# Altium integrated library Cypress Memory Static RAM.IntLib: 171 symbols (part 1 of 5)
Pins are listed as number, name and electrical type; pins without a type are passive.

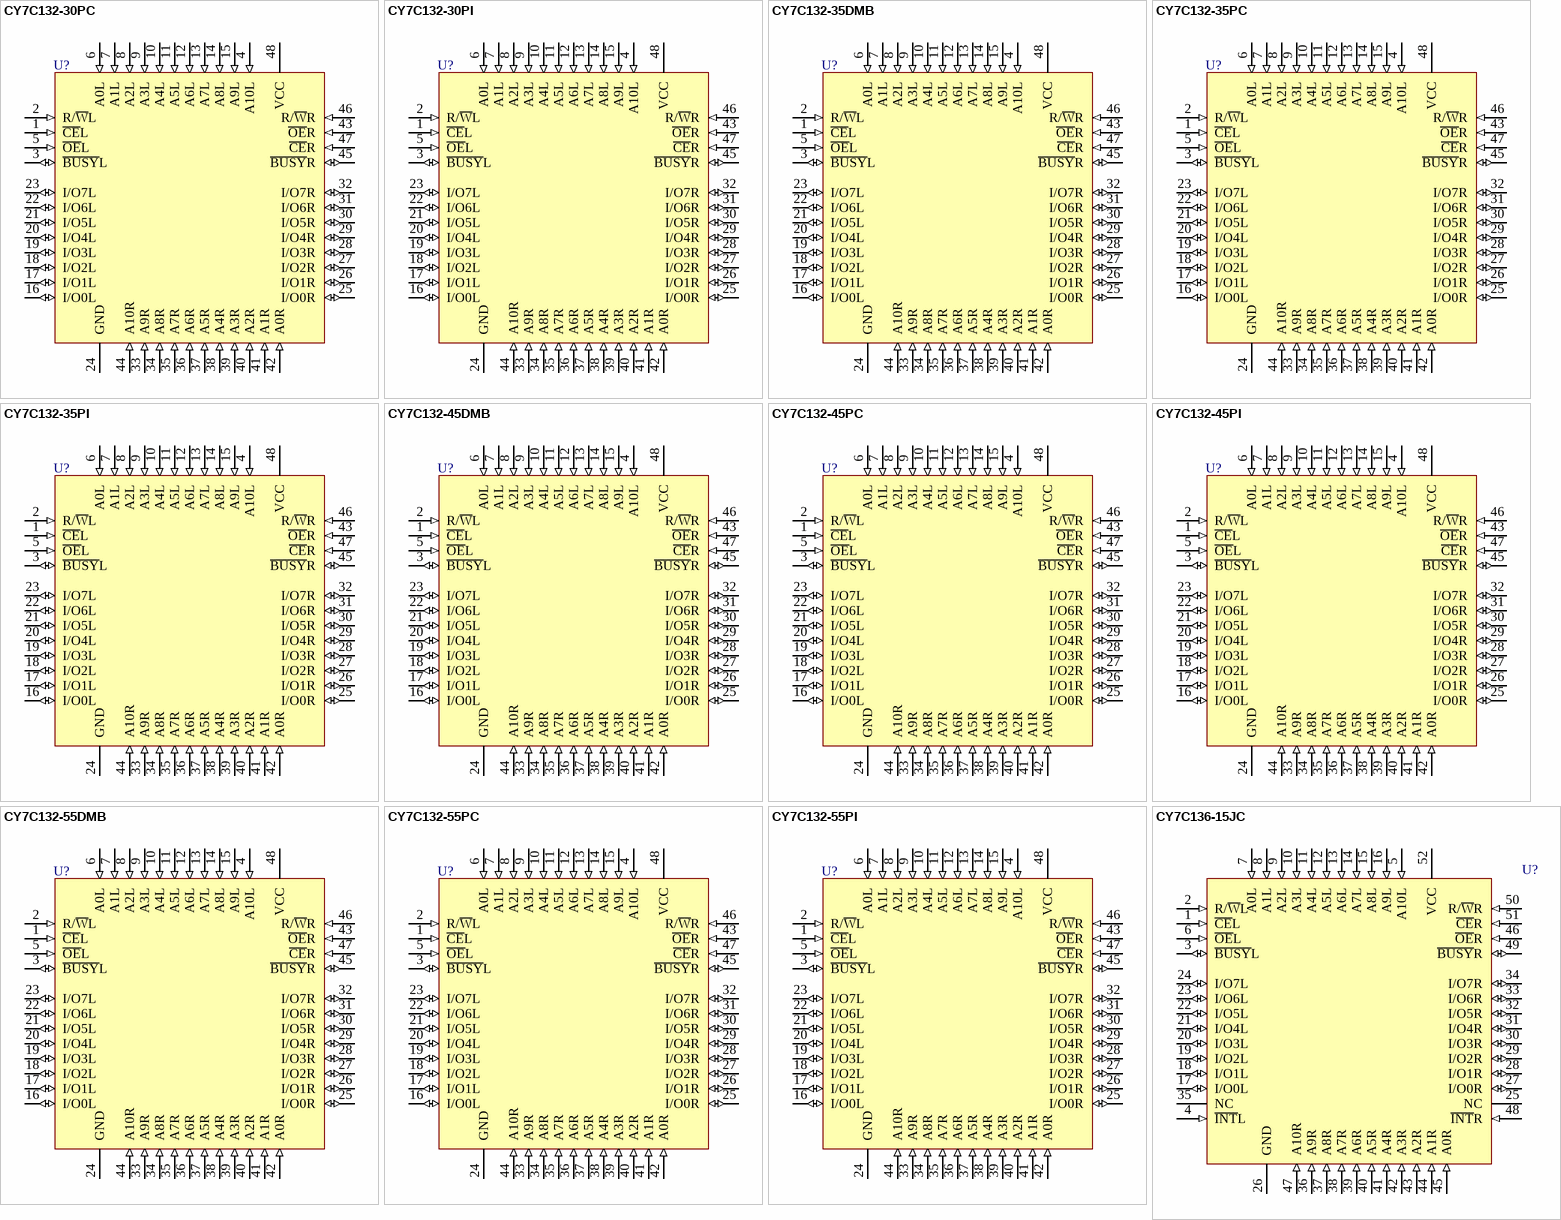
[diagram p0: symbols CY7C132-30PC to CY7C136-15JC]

## CY7C132-30PC
designator U?
2K x 8 Dual-Port Static RAM
footprint P25 (DIP, Molded; 48 Leads; Row Spacing 15.24 mm; Pitch 2.54 mm)
3D model P25 (DIP, Molded; 48 Leads; Row Spacing 15.24 mm; Pitch 2.54 mm)
pins: 1 ~{CE}L (in), 2 R/~{W}L (in), 3 ~{BUSY}L (io), 4 A10L (in), 5 ~{OE}L (in), 6 A0L (in), 7 A1L (in), 8 A2L (in), 9 A3L (in), 10 A4L (in), 11 A5L (in), 12 A6L (in), 13 A7L (in), 14 A8L (in), 15 A9L (in), 16 I/O0L (io), 17 I/O1L (io), 18 I/O2L (io), 19 I/O3L (io), 20 I/O4L (io), 21 I/O5L (io), 22 I/O6L (io), 23 I/O7L (io), 24 GND (power), 25 I/O0R (io), 26 I/O1R (io), 27 I/O2R (io), 28 I/O3R (io), 29 I/O4R (io), 30 I/O5R (io), 31 I/O6R (io), 32 I/O7R (io), 33 A9R (in), 34 A8R (in), 35 A7R (in), 36 A6R (in), 37 A5R (in), 38 A4R (in), 39 A3R (in), 40 A2R (in), 41 A1R (in), 42 A0R (in), 43 ~{OE}R (in), 44 A10R (in), 45 ~{BUSY}R (io), 46 R/~{W}R (in), 47 ~{CE}R (in), 48 VCC (power)

## CY7C132-30PI
designator U?
2K x 8 Dual-Port Static RAM
footprint P25 (DIP, Molded; 48 Leads; Row Spacing 15.24 mm; Pitch 2.54 mm)
3D model P25 (DIP, Molded; 48 Leads; Row Spacing 15.24 mm; Pitch 2.54 mm)
pins: 1 ~{CE}L (in), 2 R/~{W}L (in), 3 ~{BUSY}L (io), 4 A10L (in), 5 ~{OE}L (in), 6 A0L (in), 7 A1L (in), 8 A2L (in), 9 A3L (in), 10 A4L (in), 11 A5L (in), 12 A6L (in), 13 A7L (in), 14 A8L (in), 15 A9L (in), 16 I/O0L (io), 17 I/O1L (io), 18 I/O2L (io), 19 I/O3L (io), 20 I/O4L (io), 21 I/O5L (io), 22 I/O6L (io), 23 I/O7L (io), 24 GND (power), 25 I/O0R (io), 26 I/O1R (io), 27 I/O2R (io), 28 I/O3R (io), 29 I/O4R (io), 30 I/O5R (io), 31 I/O6R (io), 32 I/O7R (io), 33 A9R (in), 34 A8R (in), 35 A7R (in), 36 A6R (in), 37 A5R (in), 38 A4R (in), 39 A3R (in), 40 A2R (in), 41 A1R (in), 42 A0R (in), 43 ~{OE}R (in), 44 A10R (in), 45 ~{BUSY}R (io), 46 R/~{W}R (in), 47 ~{CE}R (in), 48 VCC (power)

## CY7C132-35DMB
designator U?
2K x 8 Dual-Port Static RAM
footprint D26 (DIP, Sidebraze; 48 Leads; Row Spacing 15.24 mm; Pitch 2.54 mm)
3D model P25 (DIP, Sidebraze; 48 Leads; Row Spacing 15.24 mm; Pitch 2.54 mm)
pins: 1 ~{CE}L (in), 2 R/~{W}L (in), 3 ~{BUSY}L (io), 4 A10L (in), 5 ~{OE}L (in), 6 A0L (in), 7 A1L (in), 8 A2L (in), 9 A3L (in), 10 A4L (in), 11 A5L (in), 12 A6L (in), 13 A7L (in), 14 A8L (in), 15 A9L (in), 16 I/O0L (io), 17 I/O1L (io), 18 I/O2L (io), 19 I/O3L (io), 20 I/O4L (io), 21 I/O5L (io), 22 I/O6L (io), 23 I/O7L (io), 24 GND (power), 25 I/O0R (io), 26 I/O1R (io), 27 I/O2R (io), 28 I/O3R (io), 29 I/O4R (io), 30 I/O5R (io), 31 I/O6R (io), 32 I/O7R (io), 33 A9R (in), 34 A8R (in), 35 A7R (in), 36 A6R (in), 37 A5R (in), 38 A4R (in), 39 A3R (in), 40 A2R (in), 41 A1R (in), 42 A0R (in), 43 ~{OE}R (in), 44 A10R (in), 45 ~{BUSY}R (io), 46 R/~{W}R (in), 47 ~{CE}R (in), 48 VCC (power)

## CY7C132-35PC
designator U?
2K x 8 Dual-Port Static RAM
footprint P25 (DIP, Molded; 48 Leads; Row Spacing 15.24 mm; Pitch 2.54 mm)
3D model P25 (DIP, Molded; 48 Leads; Row Spacing 15.24 mm; Pitch 2.54 mm)
pins: 1 ~{CE}L (in), 2 R/~{W}L (in), 3 ~{BUSY}L (io), 4 A10L (in), 5 ~{OE}L (in), 6 A0L (in), 7 A1L (in), 8 A2L (in), 9 A3L (in), 10 A4L (in), 11 A5L (in), 12 A6L (in), 13 A7L (in), 14 A8L (in), 15 A9L (in), 16 I/O0L (io), 17 I/O1L (io), 18 I/O2L (io), 19 I/O3L (io), 20 I/O4L (io), 21 I/O5L (io), 22 I/O6L (io), 23 I/O7L (io), 24 GND (power), 25 I/O0R (io), 26 I/O1R (io), 27 I/O2R (io), 28 I/O3R (io), 29 I/O4R (io), 30 I/O5R (io), 31 I/O6R (io), 32 I/O7R (io), 33 A9R (in), 34 A8R (in), 35 A7R (in), 36 A6R (in), 37 A5R (in), 38 A4R (in), 39 A3R (in), 40 A2R (in), 41 A1R (in), 42 A0R (in), 43 ~{OE}R (in), 44 A10R (in), 45 ~{BUSY}R (io), 46 R/~{W}R (in), 47 ~{CE}R (in), 48 VCC (power)

## CY7C132-35PI
designator U?
2K x 8 Dual-Port Static RAM
footprint P25 (DIP, Molded; 48 Leads; Row Spacing 15.24 mm; Pitch 2.54 mm)
3D model P25 (DIP, Molded; 48 Leads; Row Spacing 15.24 mm; Pitch 2.54 mm)
pins: 1 ~{CE}L (in), 2 R/~{W}L (in), 3 ~{BUSY}L (io), 4 A10L (in), 5 ~{OE}L (in), 6 A0L (in), 7 A1L (in), 8 A2L (in), 9 A3L (in), 10 A4L (in), 11 A5L (in), 12 A6L (in), 13 A7L (in), 14 A8L (in), 15 A9L (in), 16 I/O0L (io), 17 I/O1L (io), 18 I/O2L (io), 19 I/O3L (io), 20 I/O4L (io), 21 I/O5L (io), 22 I/O6L (io), 23 I/O7L (io), 24 GND (power), 25 I/O0R (io), 26 I/O1R (io), 27 I/O2R (io), 28 I/O3R (io), 29 I/O4R (io), 30 I/O5R (io), 31 I/O6R (io), 32 I/O7R (io), 33 A9R (in), 34 A8R (in), 35 A7R (in), 36 A6R (in), 37 A5R (in), 38 A4R (in), 39 A3R (in), 40 A2R (in), 41 A1R (in), 42 A0R (in), 43 ~{OE}R (in), 44 A10R (in), 45 ~{BUSY}R (io), 46 R/~{W}R (in), 47 ~{CE}R (in), 48 VCC (power)

## CY7C132-45DMB
designator U?
2K x 8 Dual-Port Static RAM
footprint D26 (DIP, Sidebraze; 48 Leads; Row Spacing 15.24 mm; Pitch 2.54 mm)
3D model P25 (DIP, Sidebraze; 48 Leads; Row Spacing 15.24 mm; Pitch 2.54 mm)
pins: 1 ~{CE}L (in), 2 R/~{W}L (in), 3 ~{BUSY}L (io), 4 A10L (in), 5 ~{OE}L (in), 6 A0L (in), 7 A1L (in), 8 A2L (in), 9 A3L (in), 10 A4L (in), 11 A5L (in), 12 A6L (in), 13 A7L (in), 14 A8L (in), 15 A9L (in), 16 I/O0L (io), 17 I/O1L (io), 18 I/O2L (io), 19 I/O3L (io), 20 I/O4L (io), 21 I/O5L (io), 22 I/O6L (io), 23 I/O7L (io), 24 GND (power), 25 I/O0R (io), 26 I/O1R (io), 27 I/O2R (io), 28 I/O3R (io), 29 I/O4R (io), 30 I/O5R (io), 31 I/O6R (io), 32 I/O7R (io), 33 A9R (in), 34 A8R (in), 35 A7R (in), 36 A6R (in), 37 A5R (in), 38 A4R (in), 39 A3R (in), 40 A2R (in), 41 A1R (in), 42 A0R (in), 43 ~{OE}R (in), 44 A10R (in), 45 ~{BUSY}R (io), 46 R/~{W}R (in), 47 ~{CE}R (in), 48 VCC (power)

## CY7C132-45PC
designator U?
2K x 8 Dual-Port Static RAM
footprint P25 (DIP, Molded; 48 Leads; Row Spacing 15.24 mm; Pitch 2.54 mm)
3D model P25 (DIP, Molded; 48 Leads; Row Spacing 15.24 mm; Pitch 2.54 mm)
pins: 1 ~{CE}L (in), 2 R/~{W}L (in), 3 ~{BUSY}L (io), 4 A10L (in), 5 ~{OE}L (in), 6 A0L (in), 7 A1L (in), 8 A2L (in), 9 A3L (in), 10 A4L (in), 11 A5L (in), 12 A6L (in), 13 A7L (in), 14 A8L (in), 15 A9L (in), 16 I/O0L (io), 17 I/O1L (io), 18 I/O2L (io), 19 I/O3L (io), 20 I/O4L (io), 21 I/O5L (io), 22 I/O6L (io), 23 I/O7L (io), 24 GND (power), 25 I/O0R (io), 26 I/O1R (io), 27 I/O2R (io), 28 I/O3R (io), 29 I/O4R (io), 30 I/O5R (io), 31 I/O6R (io), 32 I/O7R (io), 33 A9R (in), 34 A8R (in), 35 A7R (in), 36 A6R (in), 37 A5R (in), 38 A4R (in), 39 A3R (in), 40 A2R (in), 41 A1R (in), 42 A0R (in), 43 ~{OE}R (in), 44 A10R (in), 45 ~{BUSY}R (io), 46 R/~{W}R (in), 47 ~{CE}R (in), 48 VCC (power)

## CY7C132-45PI
designator U?
2K x 8 Dual-Port Static RAM
footprint P25 (DIP, Molded; 48 Leads; Row Spacing 15.24 mm; Pitch 2.54 mm)
3D model P25 (DIP, Molded; 48 Leads; Row Spacing 15.24 mm; Pitch 2.54 mm)
pins: 1 ~{CE}L (in), 2 R/~{W}L (in), 3 ~{BUSY}L (io), 4 A10L (in), 5 ~{OE}L (in), 6 A0L (in), 7 A1L (in), 8 A2L (in), 9 A3L (in), 10 A4L (in), 11 A5L (in), 12 A6L (in), 13 A7L (in), 14 A8L (in), 15 A9L (in), 16 I/O0L (io), 17 I/O1L (io), 18 I/O2L (io), 19 I/O3L (io), 20 I/O4L (io), 21 I/O5L (io), 22 I/O6L (io), 23 I/O7L (io), 24 GND (power), 25 I/O0R (io), 26 I/O1R (io), 27 I/O2R (io), 28 I/O3R (io), 29 I/O4R (io), 30 I/O5R (io), 31 I/O6R (io), 32 I/O7R (io), 33 A9R (in), 34 A8R (in), 35 A7R (in), 36 A6R (in), 37 A5R (in), 38 A4R (in), 39 A3R (in), 40 A2R (in), 41 A1R (in), 42 A0R (in), 43 ~{OE}R (in), 44 A10R (in), 45 ~{BUSY}R (io), 46 R/~{W}R (in), 47 ~{CE}R (in), 48 VCC (power)

## CY7C132-55DMB
designator U?
2K x 8 Dual-Port Static RAM
footprint D26 (DIP, Sidebraze; 48 Leads; Row Spacing 15.24 mm; Pitch 2.54 mm)
3D model P25 (DIP, Sidebraze; 48 Leads; Row Spacing 15.24 mm; Pitch 2.54 mm)
pins: 1 ~{CE}L (in), 2 R/~{W}L (in), 3 ~{BUSY}L (io), 4 A10L (in), 5 ~{OE}L (in), 6 A0L (in), 7 A1L (in), 8 A2L (in), 9 A3L (in), 10 A4L (in), 11 A5L (in), 12 A6L (in), 13 A7L (in), 14 A8L (in), 15 A9L (in), 16 I/O0L (io), 17 I/O1L (io), 18 I/O2L (io), 19 I/O3L (io), 20 I/O4L (io), 21 I/O5L (io), 22 I/O6L (io), 23 I/O7L (io), 24 GND (power), 25 I/O0R (io), 26 I/O1R (io), 27 I/O2R (io), 28 I/O3R (io), 29 I/O4R (io), 30 I/O5R (io), 31 I/O6R (io), 32 I/O7R (io), 33 A9R (in), 34 A8R (in), 35 A7R (in), 36 A6R (in), 37 A5R (in), 38 A4R (in), 39 A3R (in), 40 A2R (in), 41 A1R (in), 42 A0R (in), 43 ~{OE}R (in), 44 A10R (in), 45 ~{BUSY}R (io), 46 R/~{W}R (in), 47 ~{CE}R (in), 48 VCC (power)

## CY7C132-55PC
designator U?
2K x 8 Dual-Port Static RAM
footprint P25 (DIP, Molded; 48 Leads; Row Spacing 15.24 mm; Pitch 2.54 mm)
3D model P25 (DIP, Molded; 48 Leads; Row Spacing 15.24 mm; Pitch 2.54 mm)
pins: 1 ~{CE}L (in), 2 R/~{W}L (in), 3 ~{BUSY}L (io), 4 A10L (in), 5 ~{OE}L (in), 6 A0L (in), 7 A1L (in), 8 A2L (in), 9 A3L (in), 10 A4L (in), 11 A5L (in), 12 A6L (in), 13 A7L (in), 14 A8L (in), 15 A9L (in), 16 I/O0L (io), 17 I/O1L (io), 18 I/O2L (io), 19 I/O3L (io), 20 I/O4L (io), 21 I/O5L (io), 22 I/O6L (io), 23 I/O7L (io), 24 GND (power), 25 I/O0R (io), 26 I/O1R (io), 27 I/O2R (io), 28 I/O3R (io), 29 I/O4R (io), 30 I/O5R (io), 31 I/O6R (io), 32 I/O7R (io), 33 A9R (in), 34 A8R (in), 35 A7R (in), 36 A6R (in), 37 A5R (in), 38 A4R (in), 39 A3R (in), 40 A2R (in), 41 A1R (in), 42 A0R (in), 43 ~{OE}R (in), 44 A10R (in), 45 ~{BUSY}R (io), 46 R/~{W}R (in), 47 ~{CE}R (in), 48 VCC (power)

## CY7C132-55PI
designator U?
2K x 8 Dual-Port Static RAM
footprint P25 (DIP, Molded; 48 Leads; Row Spacing 15.24 mm; Pitch 2.54 mm)
3D model P25 (DIP, Molded; 48 Leads; Row Spacing 15.24 mm; Pitch 2.54 mm)
pins: 1 ~{CE}L (in), 2 R/~{W}L (in), 3 ~{BUSY}L (io), 4 A10L (in), 5 ~{OE}L (in), 6 A0L (in), 7 A1L (in), 8 A2L (in), 9 A3L (in), 10 A4L (in), 11 A5L (in), 12 A6L (in), 13 A7L (in), 14 A8L (in), 15 A9L (in), 16 I/O0L (io), 17 I/O1L (io), 18 I/O2L (io), 19 I/O3L (io), 20 I/O4L (io), 21 I/O5L (io), 22 I/O6L (io), 23 I/O7L (io), 24 GND (power), 25 I/O0R (io), 26 I/O1R (io), 27 I/O2R (io), 28 I/O3R (io), 29 I/O4R (io), 30 I/O5R (io), 31 I/O6R (io), 32 I/O7R (io), 33 A9R (in), 34 A8R (in), 35 A7R (in), 36 A6R (in), 37 A5R (in), 38 A4R (in), 39 A3R (in), 40 A2R (in), 41 A1R (in), 42 A0R (in), 43 ~{OE}R (in), 44 A10R (in), 45 ~{BUSY}R (io), 46 R/~{W}R (in), 47 ~{CE}R (in), 48 VCC (power)

## CY7C136-15JC
designator U?
2K x 8 Dual-Port Static RAM
footprint J69_N (Leaded Chip Carrier, 52-Leads, Body 19x19mm, Pitch 1.27mm, IPC Medium Density)
footprint J69_L (Leaded Chip Carrier, 52-Leads, Body 19x19mm, Pitch 1.27mm, IPC High Density)
footprint J69_M (Leaded Chip Carrier, 52-Leads, Body 19x19mm, Pitch 1.27mm, IPC Low Density)
3D model CY7C136-J69 (52-Pin Plastic Leaded Chip Carrier 1.27 mm Pitch)
pins: 1 ~{CE}L (in), 2 R/~{W}L (in), 3 ~{BUSY}L (io), 4 ~{INT}L (in), 5 A10L (in), 6 ~{OE}L (in), 7 A0L (in), 8 A1L (in), 9 A2L (in), 10 A3L (in), 11 A4L (in), 12 A5L (in), 13 A6L (in), 14 A7L (in), 15 A8L (in), 16 A9L (in), 17 I/O0L (io), 18 I/O1L (io), 19 I/O2L (io), 20 I/O3L (io), 21 I/O4L (io), 22 I/O5L (io), 23 I/O6L (io), 24 I/O7L (io), 25 NC, 26 GND (power), 27 I/O0R (io), 28 I/O1R (io), 29 I/O2R (io), 30 I/O3R (io), 31 I/O4R (io), 32 I/O5R (io), 33 I/O6R (io), 34 I/O7R (io), 35 NC, 36 A9R (in), 37 A8R (in), 38 A7R (in), 39 A6R (in), 40 A5R (in), 41 A4R (in), 42 A3R (in), 43 A2R (in), 44 A1R (in), 45 A0R (in), 46 ~{OE}R (in), 47 A10R (in), 48 ~{INT}R (in), 49 ~{BUSY}R (io), 50 R/~{W}R (in), 51 ~{CE}R (in), 52 VCC (power)

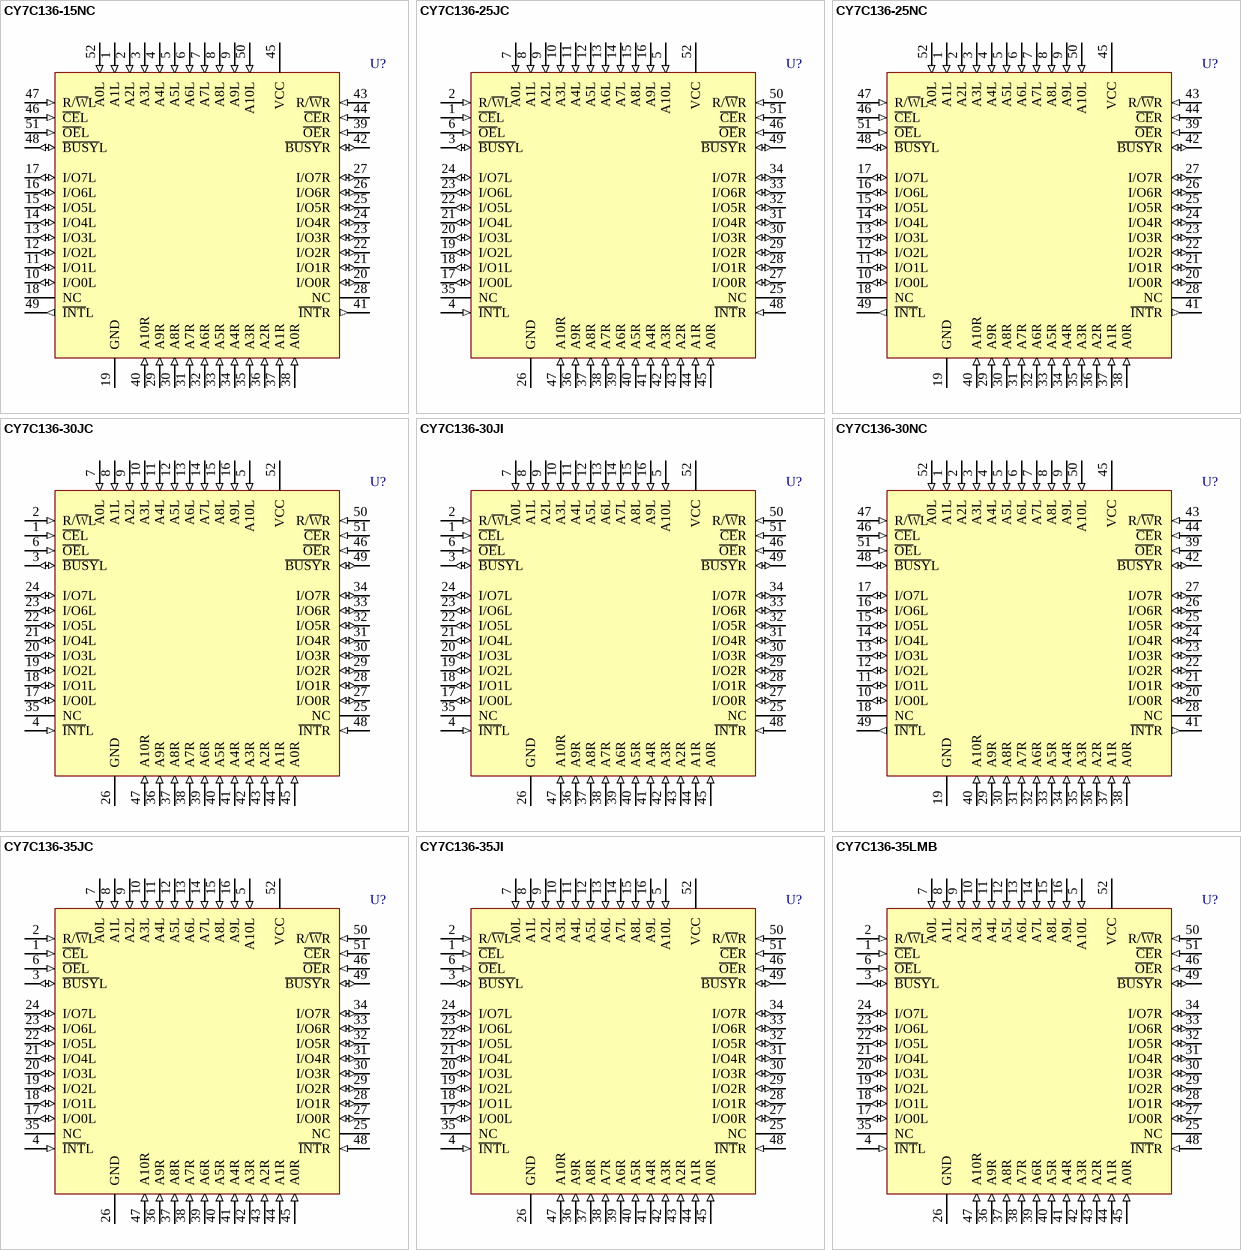
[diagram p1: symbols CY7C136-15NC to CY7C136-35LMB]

## CY7C136-15NC
designator U?
2K x 8 Dual-Port Static RAM
footprint N52_N (QFP, 52-Leads, Body 10 x 10mm, Pitch 0.65mm, IPC Medium Density)
footprint N52_L (QFP, 52-Leads, Body 10 x 10mm, Pitch 0.65mm, IPC High Density)
footprint N52_M (QFP, 52-Leads, Body 10 x 10mm, Pitch 0.65mm, IPC Low Density)
3D model CY7C136-N52 (52-Pin Plastic Quad Flat Pack 0.65 mm Pitch)
pins: 1 A1L (in), 2 A2L (in), 3 A3L (in), 4 A4L (in), 5 A5L (in), 6 A6L (in), 7 A7L (in), 8 A8L (in), 9 A9L (in), 10 I/O0L (io), 11 I/O1L (io), 12 I/O2L (io), 13 I/O3L (io), 14 I/O4L (io), 15 I/O5L (io), 16 I/O6L (io), 17 I/O7L (io), 18 NC, 19 GND (power), 20 I/O0R (io), 21 I/O1R (io), 22 I/O2R (io), 23 I/O3R (io), 24 I/O4R (io), 25 I/O5R (io), 26 I/O6R (io), 27 I/O7R (io), 28 NC, 29 A9R (in), 30 A8R (in), 31 A7R (in), 32 A6R (in), 33 A5R (in), 34 A4R (in), 35 A3R (in), 36 A2R (in), 37 A1R (in), 38 A0R (in), 39 ~{OE}R (in), 40 A10R (in), 41 ~{INT}R (out), 42 ~{BUSY}R (io), 43 R/~{W}R (in), 44 ~{CE}R (in), 45 VCC (power), 46 ~{CE}L (in), 47 R/~{W}L (in), 48 ~{BUSY}L (io), 49 ~{INT}L (out), 50 A10L (in), 51 ~{OE}L (in), 52 A0L (in)

## CY7C136-25JC
designator U?
2K x 8 Dual-Port Static RAM
footprint J69_N (Leaded Chip Carrier, 52-Leads, Body 19x19mm, Pitch 1.27mm, IPC Medium Density)
footprint J69_L (Leaded Chip Carrier, 52-Leads, Body 19x19mm, Pitch 1.27mm, IPC High Density)
footprint J69_M (Leaded Chip Carrier, 52-Leads, Body 19x19mm, Pitch 1.27mm, IPC Low Density)
3D model CY7C136-J69 (52-Pin Plastic Leaded Chip Carrier 1.27 mm Pitch)
pins: 1 ~{CE}L (in), 2 R/~{W}L (in), 3 ~{BUSY}L (io), 4 ~{INT}L (in), 5 A10L (in), 6 ~{OE}L (in), 7 A0L (in), 8 A1L (in), 9 A2L (in), 10 A3L (in), 11 A4L (in), 12 A5L (in), 13 A6L (in), 14 A7L (in), 15 A8L (in), 16 A9L (in), 17 I/O0L (io), 18 I/O1L (io), 19 I/O2L (io), 20 I/O3L (io), 21 I/O4L (io), 22 I/O5L (io), 23 I/O6L (io), 24 I/O7L (io), 25 NC, 26 GND (power), 27 I/O0R (io), 28 I/O1R (io), 29 I/O2R (io), 30 I/O3R (io), 31 I/O4R (io), 32 I/O5R (io), 33 I/O6R (io), 34 I/O7R (io), 35 NC, 36 A9R (in), 37 A8R (in), 38 A7R (in), 39 A6R (in), 40 A5R (in), 41 A4R (in), 42 A3R (in), 43 A2R (in), 44 A1R (in), 45 A0R (in), 46 ~{OE}R (in), 47 A10R (in), 48 ~{INT}R (in), 49 ~{BUSY}R (io), 50 R/~{W}R (in), 51 ~{CE}R (in), 52 VCC (power)

## CY7C136-25NC
designator U?
2K x 8 Dual-Port Static RAM
footprint N52_N (QFP, 52-Leads, Body 10 x 10mm, Pitch 0.65mm, IPC Medium Density)
footprint N52_L (QFP, 52-Leads, Body 10 x 10mm, Pitch 0.65mm, IPC High Density)
footprint N52_M (QFP, 52-Leads, Body 10 x 10mm, Pitch 0.65mm, IPC Low Density)
3D model CY7C136-N52 (52-Pin Plastic Quad Flat Pack 0.65 mm Pitch)
pins: 1 A1L (in), 2 A2L (in), 3 A3L (in), 4 A4L (in), 5 A5L (in), 6 A6L (in), 7 A7L (in), 8 A8L (in), 9 A9L (in), 10 I/O0L (io), 11 I/O1L (io), 12 I/O2L (io), 13 I/O3L (io), 14 I/O4L (io), 15 I/O5L (io), 16 I/O6L (io), 17 I/O7L (io), 18 NC, 19 GND (power), 20 I/O0R (io), 21 I/O1R (io), 22 I/O2R (io), 23 I/O3R (io), 24 I/O4R (io), 25 I/O5R (io), 26 I/O6R (io), 27 I/O7R (io), 28 NC, 29 A9R (in), 30 A8R (in), 31 A7R (in), 32 A6R (in), 33 A5R (in), 34 A4R (in), 35 A3R (in), 36 A2R (in), 37 A1R (in), 38 A0R (in), 39 ~{OE}R (in), 40 A10R (in), 41 ~{INT}R (out), 42 ~{BUSY}R (io), 43 R/~{W}R (in), 44 ~{CE}R (in), 45 VCC (power), 46 ~{CE}L (in), 47 R/~{W}L (in), 48 ~{BUSY}L (io), 49 ~{INT}L (out), 50 A10L (in), 51 ~{OE}L (in), 52 A0L (in)

## CY7C136-30JC
designator U?
2K x 8 Dual-Port Static RAM
footprint J69_N (Leaded Chip Carrier, 52-Leads, Body 19x19mm, Pitch 1.27mm, IPC Medium Density)
footprint J69_L (Leaded Chip Carrier, 52-Leads, Body 19x19mm, Pitch 1.27mm, IPC High Density)
footprint J69_M (Leaded Chip Carrier, 52-Leads, Body 19x19mm, Pitch 1.27mm, IPC Low Density)
3D model CY7C136-J69 (52-Pin Plastic Leaded Chip Carrier 1.27 mm Pitch)
pins: 1 ~{CE}L (in), 2 R/~{W}L (in), 3 ~{BUSY}L (io), 4 ~{INT}L (in), 5 A10L (in), 6 ~{OE}L (in), 7 A0L (in), 8 A1L (in), 9 A2L (in), 10 A3L (in), 11 A4L (in), 12 A5L (in), 13 A6L (in), 14 A7L (in), 15 A8L (in), 16 A9L (in), 17 I/O0L (io), 18 I/O1L (io), 19 I/O2L (io), 20 I/O3L (io), 21 I/O4L (io), 22 I/O5L (io), 23 I/O6L (io), 24 I/O7L (io), 25 NC, 26 GND (power), 27 I/O0R (io), 28 I/O1R (io), 29 I/O2R (io), 30 I/O3R (io), 31 I/O4R (io), 32 I/O5R (io), 33 I/O6R (io), 34 I/O7R (io), 35 NC, 36 A9R (in), 37 A8R (in), 38 A7R (in), 39 A6R (in), 40 A5R (in), 41 A4R (in), 42 A3R (in), 43 A2R (in), 44 A1R (in), 45 A0R (in), 46 ~{OE}R (in), 47 A10R (in), 48 ~{INT}R (in), 49 ~{BUSY}R (io), 50 R/~{W}R (in), 51 ~{CE}R (in), 52 VCC (power)

## CY7C136-30JI
designator U?
2K x 8 Dual-Port Static RAM
footprint J69_N (Leaded Chip Carrier, 52-Leads, Body 19x19mm, Pitch 1.27mm, IPC Medium Density)
footprint J69_L (Leaded Chip Carrier, 52-Leads, Body 19x19mm, Pitch 1.27mm, IPC High Density)
footprint J69_M (Leaded Chip Carrier, 52-Leads, Body 19x19mm, Pitch 1.27mm, IPC Low Density)
3D model CY7C136-J69 (52-Pin Plastic Leaded Chip Carrier 1.27 mm Pitch)
pins: 1 ~{CE}L (in), 2 R/~{W}L (in), 3 ~{BUSY}L (io), 4 ~{INT}L (in), 5 A10L (in), 6 ~{OE}L (in), 7 A0L (in), 8 A1L (in), 9 A2L (in), 10 A3L (in), 11 A4L (in), 12 A5L (in), 13 A6L (in), 14 A7L (in), 15 A8L (in), 16 A9L (in), 17 I/O0L (io), 18 I/O1L (io), 19 I/O2L (io), 20 I/O3L (io), 21 I/O4L (io), 22 I/O5L (io), 23 I/O6L (io), 24 I/O7L (io), 25 NC, 26 GND (power), 27 I/O0R (io), 28 I/O1R (io), 29 I/O2R (io), 30 I/O3R (io), 31 I/O4R (io), 32 I/O5R (io), 33 I/O6R (io), 34 I/O7R (io), 35 NC, 36 A9R (in), 37 A8R (in), 38 A7R (in), 39 A6R (in), 40 A5R (in), 41 A4R (in), 42 A3R (in), 43 A2R (in), 44 A1R (in), 45 A0R (in), 46 ~{OE}R (in), 47 A10R (in), 48 ~{INT}R (in), 49 ~{BUSY}R (io), 50 R/~{W}R (in), 51 ~{CE}R (in), 52 VCC (power)

## CY7C136-30NC
designator U?
2K x 8 Dual-Port Static RAM
footprint N52_N (QFP, 52-Leads, Body 10 x 10mm, Pitch 0.65mm, IPC Medium Density)
footprint N52_L (QFP, 52-Leads, Body 10 x 10mm, Pitch 0.65mm, IPC High Density)
footprint N52_M (QFP, 52-Leads, Body 10 x 10mm, Pitch 0.65mm, IPC Low Density)
3D model CY7C136-N52 (52-Pin Plastic Quad Flat Pack 0.65 mm Pitch)
pins: 1 A1L (in), 2 A2L (in), 3 A3L (in), 4 A4L (in), 5 A5L (in), 6 A6L (in), 7 A7L (in), 8 A8L (in), 9 A9L (in), 10 I/O0L (io), 11 I/O1L (io), 12 I/O2L (io), 13 I/O3L (io), 14 I/O4L (io), 15 I/O5L (io), 16 I/O6L (io), 17 I/O7L (io), 18 NC, 19 GND (power), 20 I/O0R (io), 21 I/O1R (io), 22 I/O2R (io), 23 I/O3R (io), 24 I/O4R (io), 25 I/O5R (io), 26 I/O6R (io), 27 I/O7R (io), 28 NC, 29 A9R (in), 30 A8R (in), 31 A7R (in), 32 A6R (in), 33 A5R (in), 34 A4R (in), 35 A3R (in), 36 A2R (in), 37 A1R (in), 38 A0R (in), 39 ~{OE}R (in), 40 A10R (in), 41 ~{INT}R (out), 42 ~{BUSY}R (io), 43 R/~{W}R (in), 44 ~{CE}R (in), 45 VCC (power), 46 ~{CE}L (in), 47 R/~{W}L (in), 48 ~{BUSY}L (io), 49 ~{INT}L (out), 50 A10L (in), 51 ~{OE}L (in), 52 A0L (in)

## CY7C136-35JC
designator U?
2K x 8 Dual-Port Static RAM
footprint J69_N (Leaded Chip Carrier, 52-Leads, Body 19x19mm, Pitch 1.27mm, IPC Medium Density)
footprint J69_L (Leaded Chip Carrier, 52-Leads, Body 19x19mm, Pitch 1.27mm, IPC High Density)
footprint J69_M (Leaded Chip Carrier, 52-Leads, Body 19x19mm, Pitch 1.27mm, IPC Low Density)
3D model CY7C136-J69 (52-Pin Plastic Leaded Chip Carrier 1.27 mm Pitch)
pins: 1 ~{CE}L (in), 2 R/~{W}L (in), 3 ~{BUSY}L (io), 4 ~{INT}L (in), 5 A10L (in), 6 ~{OE}L (in), 7 A0L (in), 8 A1L (in), 9 A2L (in), 10 A3L (in), 11 A4L (in), 12 A5L (in), 13 A6L (in), 14 A7L (in), 15 A8L (in), 16 A9L (in), 17 I/O0L (io), 18 I/O1L (io), 19 I/O2L (io), 20 I/O3L (io), 21 I/O4L (io), 22 I/O5L (io), 23 I/O6L (io), 24 I/O7L (io), 25 NC, 26 GND (power), 27 I/O0R (io), 28 I/O1R (io), 29 I/O2R (io), 30 I/O3R (io), 31 I/O4R (io), 32 I/O5R (io), 33 I/O6R (io), 34 I/O7R (io), 35 NC, 36 A9R (in), 37 A8R (in), 38 A7R (in), 39 A6R (in), 40 A5R (in), 41 A4R (in), 42 A3R (in), 43 A2R (in), 44 A1R (in), 45 A0R (in), 46 ~{OE}R (in), 47 A10R (in), 48 ~{INT}R (in), 49 ~{BUSY}R (io), 50 R/~{W}R (in), 51 ~{CE}R (in), 52 VCC (power)

## CY7C136-35JI
designator U?
2K x 8 Dual-Port Static RAM
footprint J69_N (Leaded Chip Carrier, 52-Leads, Body 19x19mm, Pitch 1.27mm, IPC Medium Density)
footprint J69_L (Leaded Chip Carrier, 52-Leads, Body 19x19mm, Pitch 1.27mm, IPC High Density)
footprint J69_M (Leaded Chip Carrier, 52-Leads, Body 19x19mm, Pitch 1.27mm, IPC Low Density)
3D model CY7C136-J69 (52-Pin Plastic Leaded Chip Carrier 1.27 mm Pitch)
pins: 1 ~{CE}L (in), 2 R/~{W}L (in), 3 ~{BUSY}L (io), 4 ~{INT}L (in), 5 A10L (in), 6 ~{OE}L (in), 7 A0L (in), 8 A1L (in), 9 A2L (in), 10 A3L (in), 11 A4L (in), 12 A5L (in), 13 A6L (in), 14 A7L (in), 15 A8L (in), 16 A9L (in), 17 I/O0L (io), 18 I/O1L (io), 19 I/O2L (io), 20 I/O3L (io), 21 I/O4L (io), 22 I/O5L (io), 23 I/O6L (io), 24 I/O7L (io), 25 NC, 26 GND (power), 27 I/O0R (io), 28 I/O1R (io), 29 I/O2R (io), 30 I/O3R (io), 31 I/O4R (io), 32 I/O5R (io), 33 I/O6R (io), 34 I/O7R (io), 35 NC, 36 A9R (in), 37 A8R (in), 38 A7R (in), 39 A6R (in), 40 A5R (in), 41 A4R (in), 42 A3R (in), 43 A2R (in), 44 A1R (in), 45 A0R (in), 46 ~{OE}R (in), 47 A10R (in), 48 ~{INT}R (in), 49 ~{BUSY}R (io), 50 R/~{W}R (in), 51 ~{CE}R (in), 52 VCC (power)

## CY7C136-35LMB
designator U?
2K x 8 Dual-Port Static RAM
footprint L69 (Leadless Chip Carrier; 52 Terminals; Body 19.1 x 19.1 mm)
pins: 1 ~{CE}L (in), 2 R/~{W}L (in), 3 ~{BUSY}L (io), 4 ~{INT}L (in), 5 A10L (in), 6 ~{OE}L (in), 7 A0L (in), 8 A1L (in), 9 A2L (in), 10 A3L (in), 11 A4L (in), 12 A5L (in), 13 A6L (in), 14 A7L (in), 15 A8L (in), 16 A9L (in), 17 I/O0L (io), 18 I/O1L (io), 19 I/O2L (io), 20 I/O3L (io), 21 I/O4L (io), 22 I/O5L (io), 23 I/O6L (io), 24 I/O7L (io), 25 NC, 26 GND (power), 27 I/O0R (io), 28 I/O1R (io), 29 I/O2R (io), 30 I/O3R (io), 31 I/O4R (io), 32 I/O5R (io), 33 I/O6R (io), 34 I/O7R (io), 35 NC, 36 A9R (in), 37 A8R (in), 38 A7R (in), 39 A6R (in), 40 A5R (in), 41 A4R (in), 42 A3R (in), 43 A2R (in), 44 A1R (in), 45 A0R (in), 46 ~{OE}R (in), 47 A10R (in), 48 ~{INT}R (in), 49 ~{BUSY}R (io), 50 R/~{W}R (in), 51 ~{CE}R (in), 52 VCC (power)

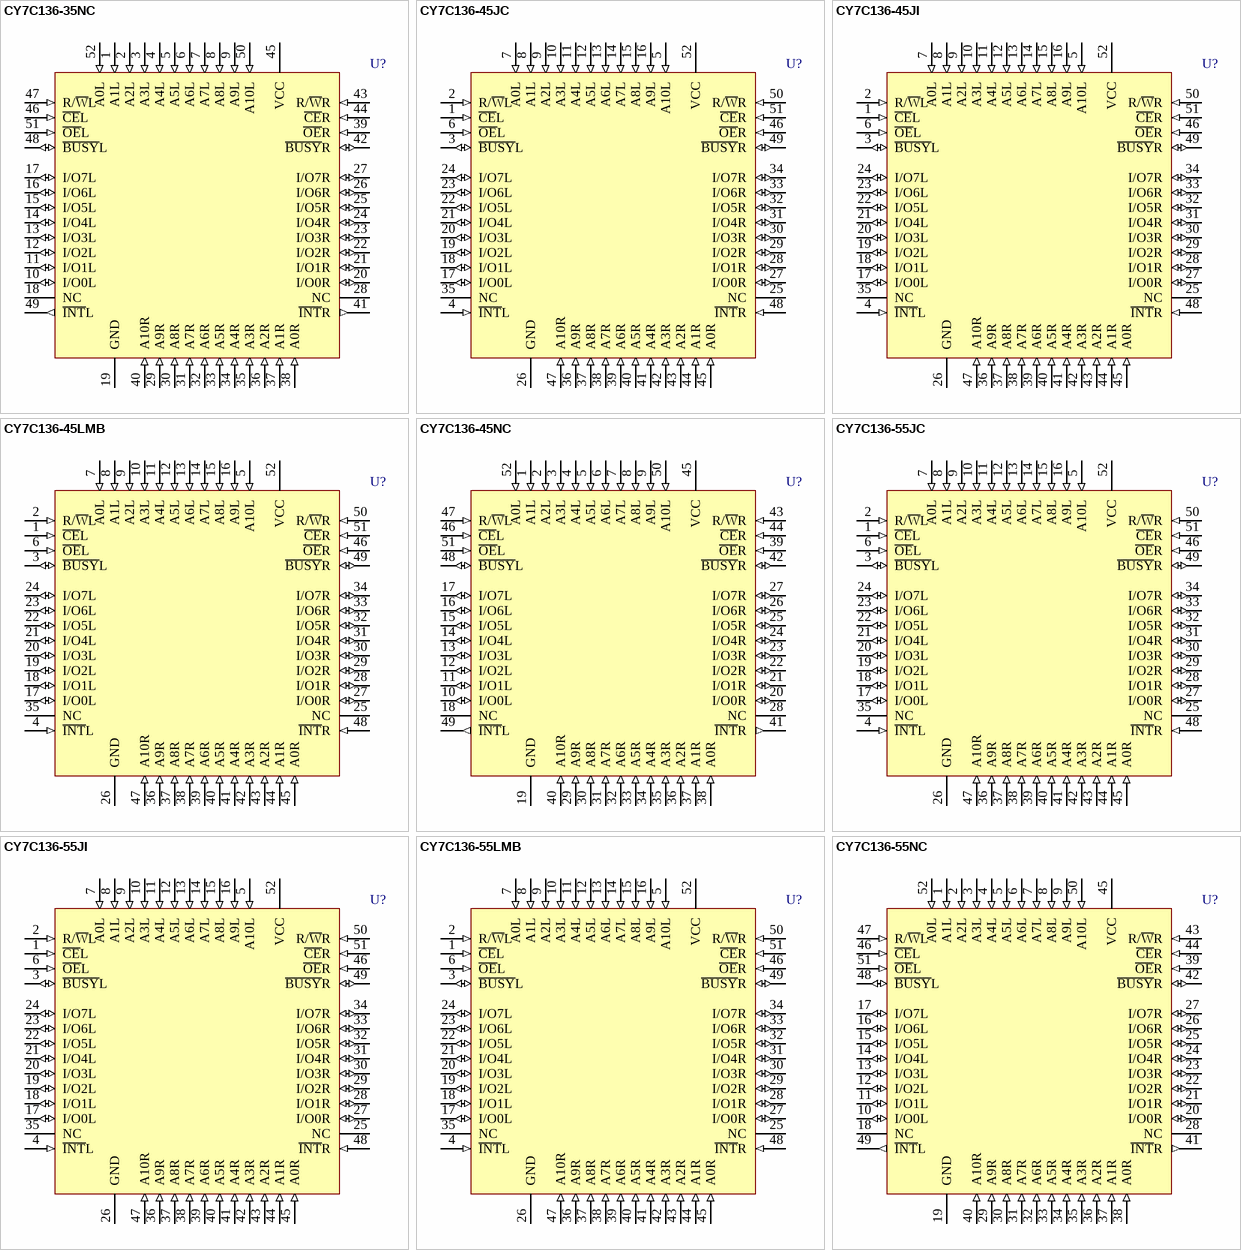
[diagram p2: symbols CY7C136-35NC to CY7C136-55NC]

## CY7C136-35NC
designator U?
2K x 8 Dual-Port Static RAM
footprint N52_N (QFP, 52-Leads, Body 10 x 10mm, Pitch 0.65mm, IPC Medium Density)
footprint N52_L (QFP, 52-Leads, Body 10 x 10mm, Pitch 0.65mm, IPC High Density)
footprint N52_M (QFP, 52-Leads, Body 10 x 10mm, Pitch 0.65mm, IPC Low Density)
3D model CY7C136-N52 (52-Pin Plastic Quad Flat Pack 0.65 mm Pitch)
pins: 1 A1L (in), 2 A2L (in), 3 A3L (in), 4 A4L (in), 5 A5L (in), 6 A6L (in), 7 A7L (in), 8 A8L (in), 9 A9L (in), 10 I/O0L (io), 11 I/O1L (io), 12 I/O2L (io), 13 I/O3L (io), 14 I/O4L (io), 15 I/O5L (io), 16 I/O6L (io), 17 I/O7L (io), 18 NC, 19 GND (power), 20 I/O0R (io), 21 I/O1R (io), 22 I/O2R (io), 23 I/O3R (io), 24 I/O4R (io), 25 I/O5R (io), 26 I/O6R (io), 27 I/O7R (io), 28 NC, 29 A9R (in), 30 A8R (in), 31 A7R (in), 32 A6R (in), 33 A5R (in), 34 A4R (in), 35 A3R (in), 36 A2R (in), 37 A1R (in), 38 A0R (in), 39 ~{OE}R (in), 40 A10R (in), 41 ~{INT}R (out), 42 ~{BUSY}R (io), 43 R/~{W}R (in), 44 ~{CE}R (in), 45 VCC (power), 46 ~{CE}L (in), 47 R/~{W}L (in), 48 ~{BUSY}L (io), 49 ~{INT}L (out), 50 A10L (in), 51 ~{OE}L (in), 52 A0L (in)

## CY7C136-45JC
designator U?
2K x 8 Dual-Port Static RAM
footprint J69_N (Leaded Chip Carrier, 52-Leads, Body 19x19mm, Pitch 1.27mm, IPC Medium Density)
footprint J69_L (Leaded Chip Carrier, 52-Leads, Body 19x19mm, Pitch 1.27mm, IPC High Density)
footprint J69_M (Leaded Chip Carrier, 52-Leads, Body 19x19mm, Pitch 1.27mm, IPC Low Density)
3D model CY7C136-J69 (52-Pin Plastic Leaded Chip Carrier 1.27 mm Pitch)
pins: 1 ~{CE}L (in), 2 R/~{W}L (in), 3 ~{BUSY}L (io), 4 ~{INT}L (in), 5 A10L (in), 6 ~{OE}L (in), 7 A0L (in), 8 A1L (in), 9 A2L (in), 10 A3L (in), 11 A4L (in), 12 A5L (in), 13 A6L (in), 14 A7L (in), 15 A8L (in), 16 A9L (in), 17 I/O0L (io), 18 I/O1L (io), 19 I/O2L (io), 20 I/O3L (io), 21 I/O4L (io), 22 I/O5L (io), 23 I/O6L (io), 24 I/O7L (io), 25 NC, 26 GND (power), 27 I/O0R (io), 28 I/O1R (io), 29 I/O2R (io), 30 I/O3R (io), 31 I/O4R (io), 32 I/O5R (io), 33 I/O6R (io), 34 I/O7R (io), 35 NC, 36 A9R (in), 37 A8R (in), 38 A7R (in), 39 A6R (in), 40 A5R (in), 41 A4R (in), 42 A3R (in), 43 A2R (in), 44 A1R (in), 45 A0R (in), 46 ~{OE}R (in), 47 A10R (in), 48 ~{INT}R (in), 49 ~{BUSY}R (io), 50 R/~{W}R (in), 51 ~{CE}R (in), 52 VCC (power)

## CY7C136-45JI
designator U?
2K x 8 Dual-Port Static RAM
footprint J69_N (Leaded Chip Carrier, 52-Leads, Body 19x19mm, Pitch 1.27mm, IPC Medium Density)
footprint J69_L (Leaded Chip Carrier, 52-Leads, Body 19x19mm, Pitch 1.27mm, IPC High Density)
footprint J69_M (Leaded Chip Carrier, 52-Leads, Body 19x19mm, Pitch 1.27mm, IPC Low Density)
3D model CY7C136-J69 (52-Pin Plastic Leaded Chip Carrier 1.27 mm Pitch)
pins: 1 ~{CE}L (in), 2 R/~{W}L (in), 3 ~{BUSY}L (io), 4 ~{INT}L (in), 5 A10L (in), 6 ~{OE}L (in), 7 A0L (in), 8 A1L (in), 9 A2L (in), 10 A3L (in), 11 A4L (in), 12 A5L (in), 13 A6L (in), 14 A7L (in), 15 A8L (in), 16 A9L (in), 17 I/O0L (io), 18 I/O1L (io), 19 I/O2L (io), 20 I/O3L (io), 21 I/O4L (io), 22 I/O5L (io), 23 I/O6L (io), 24 I/O7L (io), 25 NC, 26 GND (power), 27 I/O0R (io), 28 I/O1R (io), 29 I/O2R (io), 30 I/O3R (io), 31 I/O4R (io), 32 I/O5R (io), 33 I/O6R (io), 34 I/O7R (io), 35 NC, 36 A9R (in), 37 A8R (in), 38 A7R (in), 39 A6R (in), 40 A5R (in), 41 A4R (in), 42 A3R (in), 43 A2R (in), 44 A1R (in), 45 A0R (in), 46 ~{OE}R (in), 47 A10R (in), 48 ~{INT}R (in), 49 ~{BUSY}R (io), 50 R/~{W}R (in), 51 ~{CE}R (in), 52 VCC (power)

## CY7C136-45LMB
designator U?
2K x 8 Dual-Port Static RAM
footprint L69 (Leadless Chip Carrier; 52 Terminals; Body 19.1 x 19.1 mm)
pins: 1 ~{CE}L (in), 2 R/~{W}L (in), 3 ~{BUSY}L (io), 4 ~{INT}L (in), 5 A10L (in), 6 ~{OE}L (in), 7 A0L (in), 8 A1L (in), 9 A2L (in), 10 A3L (in), 11 A4L (in), 12 A5L (in), 13 A6L (in), 14 A7L (in), 15 A8L (in), 16 A9L (in), 17 I/O0L (io), 18 I/O1L (io), 19 I/O2L (io), 20 I/O3L (io), 21 I/O4L (io), 22 I/O5L (io), 23 I/O6L (io), 24 I/O7L (io), 25 NC, 26 GND (power), 27 I/O0R (io), 28 I/O1R (io), 29 I/O2R (io), 30 I/O3R (io), 31 I/O4R (io), 32 I/O5R (io), 33 I/O6R (io), 34 I/O7R (io), 35 NC, 36 A9R (in), 37 A8R (in), 38 A7R (in), 39 A6R (in), 40 A5R (in), 41 A4R (in), 42 A3R (in), 43 A2R (in), 44 A1R (in), 45 A0R (in), 46 ~{OE}R (in), 47 A10R (in), 48 ~{INT}R (in), 49 ~{BUSY}R (io), 50 R/~{W}R (in), 51 ~{CE}R (in), 52 VCC (power)

## CY7C136-45NC
designator U?
2K x 8 Dual-Port Static RAM
footprint N52_N (QFP, 52-Leads, Body 10 x 10mm, Pitch 0.65mm, IPC Medium Density)
footprint N52_L (QFP, 52-Leads, Body 10 x 10mm, Pitch 0.65mm, IPC High Density)
footprint N52_M (QFP, 52-Leads, Body 10 x 10mm, Pitch 0.65mm, IPC Low Density)
3D model CY7C136-N52 (52-Pin Plastic Quad Flat Pack 0.65 mm Pitch)
pins: 1 A1L (in), 2 A2L (in), 3 A3L (in), 4 A4L (in), 5 A5L (in), 6 A6L (in), 7 A7L (in), 8 A8L (in), 9 A9L (in), 10 I/O0L (io), 11 I/O1L (io), 12 I/O2L (io), 13 I/O3L (io), 14 I/O4L (io), 15 I/O5L (io), 16 I/O6L (io), 17 I/O7L (io), 18 NC, 19 GND (power), 20 I/O0R (io), 21 I/O1R (io), 22 I/O2R (io), 23 I/O3R (io), 24 I/O4R (io), 25 I/O5R (io), 26 I/O6R (io), 27 I/O7R (io), 28 NC, 29 A9R (in), 30 A8R (in), 31 A7R (in), 32 A6R (in), 33 A5R (in), 34 A4R (in), 35 A3R (in), 36 A2R (in), 37 A1R (in), 38 A0R (in), 39 ~{OE}R (in), 40 A10R (in), 41 ~{INT}R (out), 42 ~{BUSY}R (io), 43 R/~{W}R (in), 44 ~{CE}R (in), 45 VCC (power), 46 ~{CE}L (in), 47 R/~{W}L (in), 48 ~{BUSY}L (io), 49 ~{INT}L (out), 50 A10L (in), 51 ~{OE}L (in), 52 A0L (in)

## CY7C136-55JC
designator U?
2K x 8 Dual-Port Static RAM
footprint J69_N (Leaded Chip Carrier, 52-Leads, Body 19x19mm, Pitch 1.27mm, IPC Medium Density)
footprint J69_L (Leaded Chip Carrier, 52-Leads, Body 19x19mm, Pitch 1.27mm, IPC High Density)
footprint J69_M (Leaded Chip Carrier, 52-Leads, Body 19x19mm, Pitch 1.27mm, IPC Low Density)
3D model CY7C136-J69 (52-Pin Plastic Leaded Chip Carrier 1.27 mm Pitch)
pins: 1 ~{CE}L (in), 2 R/~{W}L (in), 3 ~{BUSY}L (io), 4 ~{INT}L (in), 5 A10L (in), 6 ~{OE}L (in), 7 A0L (in), 8 A1L (in), 9 A2L (in), 10 A3L (in), 11 A4L (in), 12 A5L (in), 13 A6L (in), 14 A7L (in), 15 A8L (in), 16 A9L (in), 17 I/O0L (io), 18 I/O1L (io), 19 I/O2L (io), 20 I/O3L (io), 21 I/O4L (io), 22 I/O5L (io), 23 I/O6L (io), 24 I/O7L (io), 25 NC, 26 GND (power), 27 I/O0R (io), 28 I/O1R (io), 29 I/O2R (io), 30 I/O3R (io), 31 I/O4R (io), 32 I/O5R (io), 33 I/O6R (io), 34 I/O7R (io), 35 NC, 36 A9R (in), 37 A8R (in), 38 A7R (in), 39 A6R (in), 40 A5R (in), 41 A4R (in), 42 A3R (in), 43 A2R (in), 44 A1R (in), 45 A0R (in), 46 ~{OE}R (in), 47 A10R (in), 48 ~{INT}R (in), 49 ~{BUSY}R (io), 50 R/~{W}R (in), 51 ~{CE}R (in), 52 VCC (power)

## CY7C136-55JI
designator U?
2K x 8 Dual-Port Static RAM
footprint J69_N (Leaded Chip Carrier, 52-Leads, Body 19x19mm, Pitch 1.27mm, IPC Medium Density)
footprint J69_L (Leaded Chip Carrier, 52-Leads, Body 19x19mm, Pitch 1.27mm, IPC High Density)
footprint J69_M (Leaded Chip Carrier, 52-Leads, Body 19x19mm, Pitch 1.27mm, IPC Low Density)
3D model CY7C136-J69 (52-Pin Plastic Leaded Chip Carrier 1.27 mm Pitch)
pins: 1 ~{CE}L (in), 2 R/~{W}L (in), 3 ~{BUSY}L (io), 4 ~{INT}L (in), 5 A10L (in), 6 ~{OE}L (in), 7 A0L (in), 8 A1L (in), 9 A2L (in), 10 A3L (in), 11 A4L (in), 12 A5L (in), 13 A6L (in), 14 A7L (in), 15 A8L (in), 16 A9L (in), 17 I/O0L (io), 18 I/O1L (io), 19 I/O2L (io), 20 I/O3L (io), 21 I/O4L (io), 22 I/O5L (io), 23 I/O6L (io), 24 I/O7L (io), 25 NC, 26 GND (power), 27 I/O0R (io), 28 I/O1R (io), 29 I/O2R (io), 30 I/O3R (io), 31 I/O4R (io), 32 I/O5R (io), 33 I/O6R (io), 34 I/O7R (io), 35 NC, 36 A9R (in), 37 A8R (in), 38 A7R (in), 39 A6R (in), 40 A5R (in), 41 A4R (in), 42 A3R (in), 43 A2R (in), 44 A1R (in), 45 A0R (in), 46 ~{OE}R (in), 47 A10R (in), 48 ~{INT}R (in), 49 ~{BUSY}R (io), 50 R/~{W}R (in), 51 ~{CE}R (in), 52 VCC (power)

## CY7C136-55LMB
designator U?
2K x 8 Dual-Port Static RAM
footprint L69 (Leadless Chip Carrier; 52 Terminals; Body 19.1 x 19.1 mm)
pins: 1 ~{CE}L (in), 2 R/~{W}L (in), 3 ~{BUSY}L (io), 4 ~{INT}L (in), 5 A10L (in), 6 ~{OE}L (in), 7 A0L (in), 8 A1L (in), 9 A2L (in), 10 A3L (in), 11 A4L (in), 12 A5L (in), 13 A6L (in), 14 A7L (in), 15 A8L (in), 16 A9L (in), 17 I/O0L (io), 18 I/O1L (io), 19 I/O2L (io), 20 I/O3L (io), 21 I/O4L (io), 22 I/O5L (io), 23 I/O6L (io), 24 I/O7L (io), 25 NC, 26 GND (power), 27 I/O0R (io), 28 I/O1R (io), 29 I/O2R (io), 30 I/O3R (io), 31 I/O4R (io), 32 I/O5R (io), 33 I/O6R (io), 34 I/O7R (io), 35 NC, 36 A9R (in), 37 A8R (in), 38 A7R (in), 39 A6R (in), 40 A5R (in), 41 A4R (in), 42 A3R (in), 43 A2R (in), 44 A1R (in), 45 A0R (in), 46 ~{OE}R (in), 47 A10R (in), 48 ~{INT}R (in), 49 ~{BUSY}R (io), 50 R/~{W}R (in), 51 ~{CE}R (in), 52 VCC (power)

## CY7C136-55NC
designator U?
2K x 8 Dual-Port Static RAM
footprint N52_N (QFP, 52-Leads, Body 10 x 10mm, Pitch 0.65mm, IPC Medium Density)
footprint N52_L (QFP, 52-Leads, Body 10 x 10mm, Pitch 0.65mm, IPC High Density)
footprint N52_M (QFP, 52-Leads, Body 10 x 10mm, Pitch 0.65mm, IPC Low Density)
3D model CY7C136-N52 (52-Pin Plastic Quad Flat Pack 0.65 mm Pitch)
pins: 1 A1L (in), 2 A2L (in), 3 A3L (in), 4 A4L (in), 5 A5L (in), 6 A6L (in), 7 A7L (in), 8 A8L (in), 9 A9L (in), 10 I/O0L (io), 11 I/O1L (io), 12 I/O2L (io), 13 I/O3L (io), 14 I/O4L (io), 15 I/O5L (io), 16 I/O6L (io), 17 I/O7L (io), 18 NC, 19 GND (power), 20 I/O0R (io), 21 I/O1R (io), 22 I/O2R (io), 23 I/O3R (io), 24 I/O4R (io), 25 I/O5R (io), 26 I/O6R (io), 27 I/O7R (io), 28 NC, 29 A9R (in), 30 A8R (in), 31 A7R (in), 32 A6R (in), 33 A5R (in), 34 A4R (in), 35 A3R (in), 36 A2R (in), 37 A1R (in), 38 A0R (in), 39 ~{OE}R (in), 40 A10R (in), 41 ~{INT}R (out), 42 ~{BUSY}R (io), 43 R/~{W}R (in), 44 ~{CE}R (in), 45 VCC (power), 46 ~{CE}L (in), 47 R/~{W}L (in), 48 ~{BUSY}L (io), 49 ~{INT}L (out), 50 A10L (in), 51 ~{OE}L (in), 52 A0L (in)

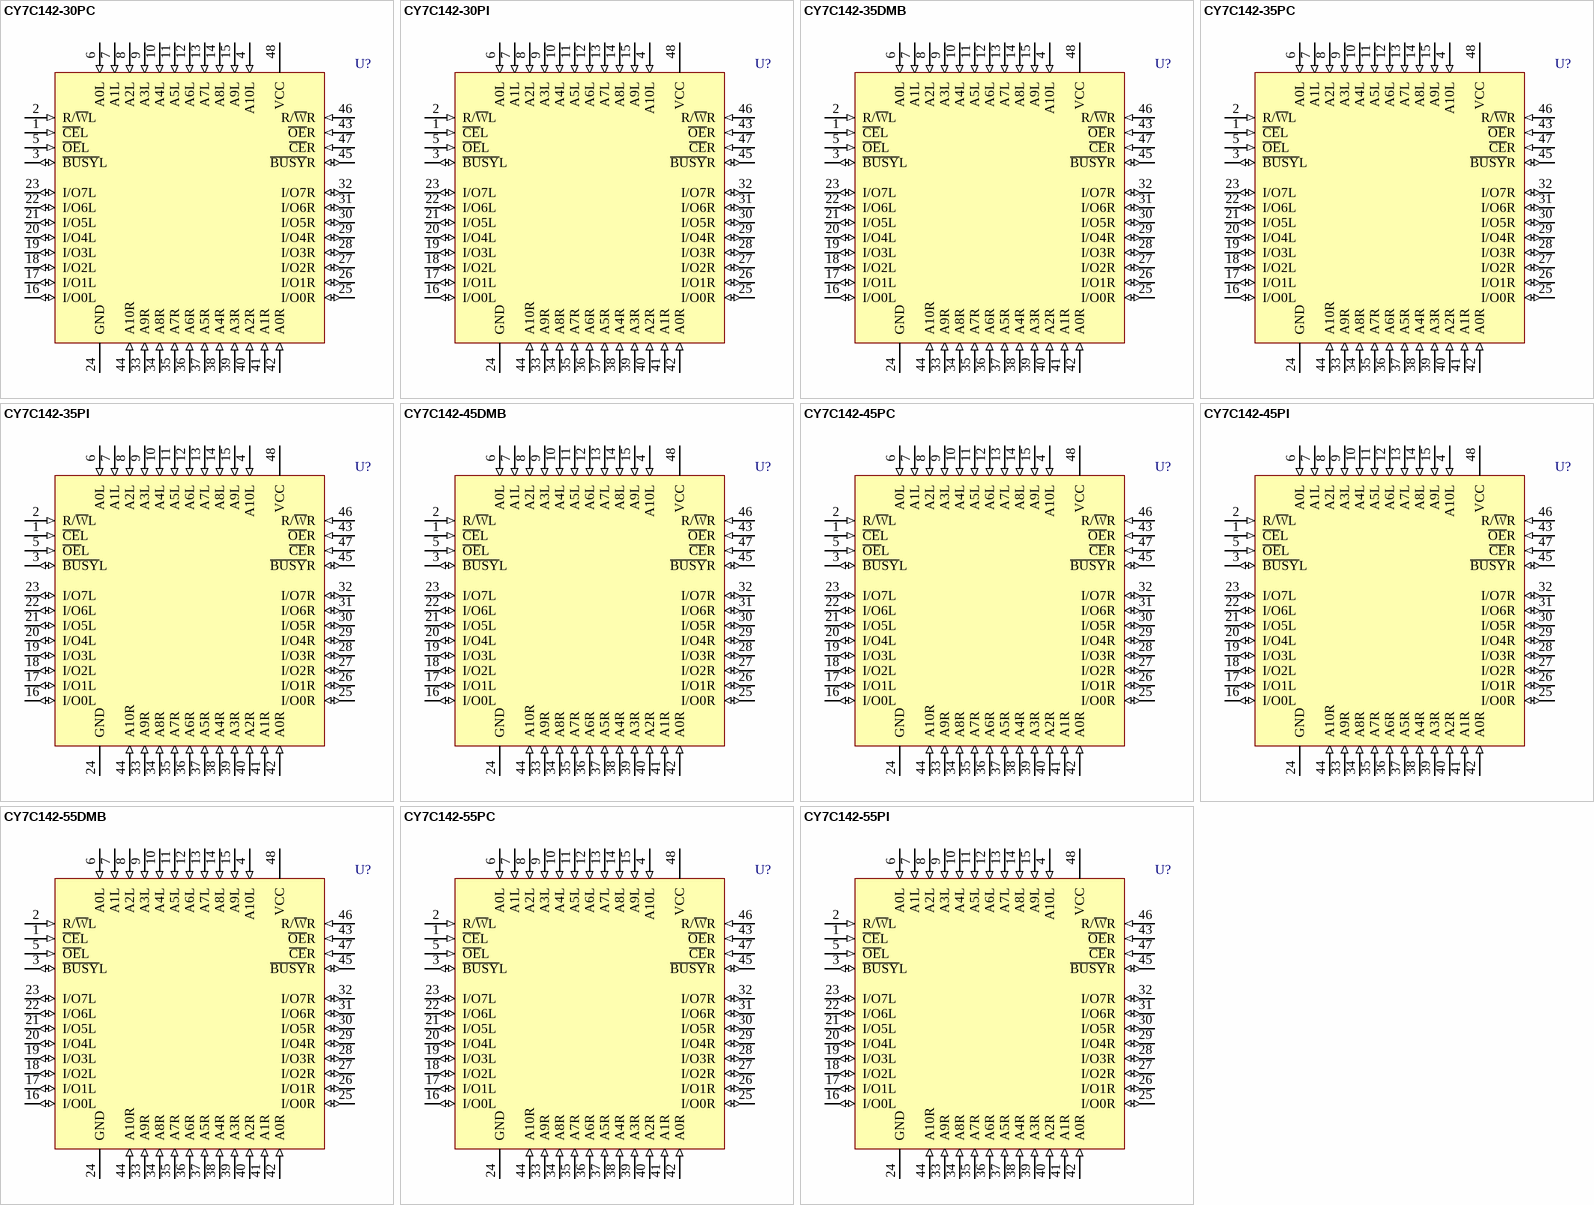
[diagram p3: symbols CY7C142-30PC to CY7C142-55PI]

## CY7C142-30PC
designator U?
2K x 8 Dual-Port Static RAM
footprint P25 (DIP, Molded; 48 Leads; Row Spacing 15.24 mm; Pitch 2.54 mm)
3D model P25 (DIP, Molded; 48 Leads; Row Spacing 15.24 mm; Pitch 2.54 mm)
pins: 1 ~{CE}L (in), 2 R/~{W}L (in), 3 ~{BUSY}L (io), 4 A10L (in), 5 ~{OE}L (in), 6 A0L (in), 7 A1L (in), 8 A2L (in), 9 A3L (in), 10 A4L (in), 11 A5L (in), 12 A6L (in), 13 A7L (in), 14 A8L (in), 15 A9L (in), 16 I/O0L (io), 17 I/O1L (io), 18 I/O2L (io), 19 I/O3L (io), 20 I/O4L (io), 21 I/O5L (io), 22 I/O6L (io), 23 I/O7L (io), 24 GND (power), 25 I/O0R (io), 26 I/O1R (io), 27 I/O2R (io), 28 I/O3R (io), 29 I/O4R (io), 30 I/O5R (io), 31 I/O6R (io), 32 I/O7R (io), 33 A9R (in), 34 A8R (in), 35 A7R (in), 36 A6R (in), 37 A5R (in), 38 A4R (in), 39 A3R (in), 40 A2R (in), 41 A1R (in), 42 A0R (in), 43 ~{OE}R (in), 44 A10R (in), 45 ~{BUSY}R (io), 46 R/~{W}R (in), 47 ~{CE}R (in), 48 VCC (power)

## CY7C142-30PI
designator U?
2K x 8 Dual-Port Static RAM
footprint P25 (DIP, Molded; 48 Leads; Row Spacing 15.24 mm; Pitch 2.54 mm)
3D model P25 (DIP, Molded; 48 Leads; Row Spacing 15.24 mm; Pitch 2.54 mm)
pins: 1 ~{CE}L (in), 2 R/~{W}L (in), 3 ~{BUSY}L (io), 4 A10L (in), 5 ~{OE}L (in), 6 A0L (in), 7 A1L (in), 8 A2L (in), 9 A3L (in), 10 A4L (in), 11 A5L (in), 12 A6L (in), 13 A7L (in), 14 A8L (in), 15 A9L (in), 16 I/O0L (io), 17 I/O1L (io), 18 I/O2L (io), 19 I/O3L (io), 20 I/O4L (io), 21 I/O5L (io), 22 I/O6L (io), 23 I/O7L (io), 24 GND (power), 25 I/O0R (io), 26 I/O1R (io), 27 I/O2R (io), 28 I/O3R (io), 29 I/O4R (io), 30 I/O5R (io), 31 I/O6R (io), 32 I/O7R (io), 33 A9R (in), 34 A8R (in), 35 A7R (in), 36 A6R (in), 37 A5R (in), 38 A4R (in), 39 A3R (in), 40 A2R (in), 41 A1R (in), 42 A0R (in), 43 ~{OE}R (in), 44 A10R (in), 45 ~{BUSY}R (io), 46 R/~{W}R (in), 47 ~{CE}R (in), 48 VCC (power)

## CY7C142-35DMB
designator U?
2K x 8 Dual-Port Static RAM
footprint D26 (DIP, Sidebraze; 48 Leads; Row Spacing 15.24 mm; Pitch 2.54 mm)
3D model P25 (DIP, Sidebraze; 48 Leads; Row Spacing 15.24 mm; Pitch 2.54 mm)
pins: 1 ~{CE}L (in), 2 R/~{W}L (in), 3 ~{BUSY}L (io), 4 A10L (in), 5 ~{OE}L (in), 6 A0L (in), 7 A1L (in), 8 A2L (in), 9 A3L (in), 10 A4L (in), 11 A5L (in), 12 A6L (in), 13 A7L (in), 14 A8L (in), 15 A9L (in), 16 I/O0L (io), 17 I/O1L (io), 18 I/O2L (io), 19 I/O3L (io), 20 I/O4L (io), 21 I/O5L (io), 22 I/O6L (io), 23 I/O7L (io), 24 GND (power), 25 I/O0R (io), 26 I/O1R (io), 27 I/O2R (io), 28 I/O3R (io), 29 I/O4R (io), 30 I/O5R (io), 31 I/O6R (io), 32 I/O7R (io), 33 A9R (in), 34 A8R (in), 35 A7R (in), 36 A6R (in), 37 A5R (in), 38 A4R (in), 39 A3R (in), 40 A2R (in), 41 A1R (in), 42 A0R (in), 43 ~{OE}R (in), 44 A10R (in), 45 ~{BUSY}R (io), 46 R/~{W}R (in), 47 ~{CE}R (in), 48 VCC (power)

## CY7C142-35PC
designator U?
2K x 8 Dual-Port Static RAM
footprint P25 (DIP, Molded; 48 Leads; Row Spacing 15.24 mm; Pitch 2.54 mm)
3D model P25 (DIP, Molded; 48 Leads; Row Spacing 15.24 mm; Pitch 2.54 mm)
pins: 1 ~{CE}L (in), 2 R/~{W}L (in), 3 ~{BUSY}L (io), 4 A10L (in), 5 ~{OE}L (in), 6 A0L (in), 7 A1L (in), 8 A2L (in), 9 A3L (in), 10 A4L (in), 11 A5L (in), 12 A6L (in), 13 A7L (in), 14 A8L (in), 15 A9L (in), 16 I/O0L (io), 17 I/O1L (io), 18 I/O2L (io), 19 I/O3L (io), 20 I/O4L (io), 21 I/O5L (io), 22 I/O6L (io), 23 I/O7L (io), 24 GND (power), 25 I/O0R (io), 26 I/O1R (io), 27 I/O2R (io), 28 I/O3R (io), 29 I/O4R (io), 30 I/O5R (io), 31 I/O6R (io), 32 I/O7R (io), 33 A9R (in), 34 A8R (in), 35 A7R (in), 36 A6R (in), 37 A5R (in), 38 A4R (in), 39 A3R (in), 40 A2R (in), 41 A1R (in), 42 A0R (in), 43 ~{OE}R (in), 44 A10R (in), 45 ~{BUSY}R (io), 46 R/~{W}R (in), 47 ~{CE}R (in), 48 VCC (power)

## CY7C142-35PI
designator U?
2K x 8 Dual-Port Static RAM
footprint P25 (DIP, Molded; 48 Leads; Row Spacing 15.24 mm; Pitch 2.54 mm)
3D model P25 (DIP, Molded; 48 Leads; Row Spacing 15.24 mm; Pitch 2.54 mm)
pins: 1 ~{CE}L (in), 2 R/~{W}L (in), 3 ~{BUSY}L (io), 4 A10L (in), 5 ~{OE}L (in), 6 A0L (in), 7 A1L (in), 8 A2L (in), 9 A3L (in), 10 A4L (in), 11 A5L (in), 12 A6L (in), 13 A7L (in), 14 A8L (in), 15 A9L (in), 16 I/O0L (io), 17 I/O1L (io), 18 I/O2L (io), 19 I/O3L (io), 20 I/O4L (io), 21 I/O5L (io), 22 I/O6L (io), 23 I/O7L (io), 24 GND (power), 25 I/O0R (io), 26 I/O1R (io), 27 I/O2R (io), 28 I/O3R (io), 29 I/O4R (io), 30 I/O5R (io), 31 I/O6R (io), 32 I/O7R (io), 33 A9R (in), 34 A8R (in), 35 A7R (in), 36 A6R (in), 37 A5R (in), 38 A4R (in), 39 A3R (in), 40 A2R (in), 41 A1R (in), 42 A0R (in), 43 ~{OE}R (in), 44 A10R (in), 45 ~{BUSY}R (io), 46 R/~{W}R (in), 47 ~{CE}R (in), 48 VCC (power)

## CY7C142-45DMB
designator U?
2K x 8 Dual-Port Static RAM
footprint D26 (DIP, Sidebraze; 48 Leads; Row Spacing 15.24 mm; Pitch 2.54 mm)
3D model P25 (DIP, Sidebraze; 48 Leads; Row Spacing 15.24 mm; Pitch 2.54 mm)
pins: 1 ~{CE}L (in), 2 R/~{W}L (in), 3 ~{BUSY}L (io), 4 A10L (in), 5 ~{OE}L (in), 6 A0L (in), 7 A1L (in), 8 A2L (in), 9 A3L (in), 10 A4L (in), 11 A5L (in), 12 A6L (in), 13 A7L (in), 14 A8L (in), 15 A9L (in), 16 I/O0L (io), 17 I/O1L (io), 18 I/O2L (io), 19 I/O3L (io), 20 I/O4L (io), 21 I/O5L (io), 22 I/O6L (io), 23 I/O7L (io), 24 GND (power), 25 I/O0R (io), 26 I/O1R (io), 27 I/O2R (io), 28 I/O3R (io), 29 I/O4R (io), 30 I/O5R (io), 31 I/O6R (io), 32 I/O7R (io), 33 A9R (in), 34 A8R (in), 35 A7R (in), 36 A6R (in), 37 A5R (in), 38 A4R (in), 39 A3R (in), 40 A2R (in), 41 A1R (in), 42 A0R (in), 43 ~{OE}R (in), 44 A10R (in), 45 ~{BUSY}R (io), 46 R/~{W}R (in), 47 ~{CE}R (in), 48 VCC (power)

## CY7C142-45PC
designator U?
2K x 8 Dual-Port Static RAM
footprint P25 (DIP, Molded; 48 Leads; Row Spacing 15.24 mm; Pitch 2.54 mm)
3D model P25 (DIP, Molded; 48 Leads; Row Spacing 15.24 mm; Pitch 2.54 mm)
pins: 1 ~{CE}L (in), 2 R/~{W}L (in), 3 ~{BUSY}L (io), 4 A10L (in), 5 ~{OE}L (in), 6 A0L (in), 7 A1L (in), 8 A2L (in), 9 A3L (in), 10 A4L (in), 11 A5L (in), 12 A6L (in), 13 A7L (in), 14 A8L (in), 15 A9L (in), 16 I/O0L (io), 17 I/O1L (io), 18 I/O2L (io), 19 I/O3L (io), 20 I/O4L (io), 21 I/O5L (io), 22 I/O6L (io), 23 I/O7L (io), 24 GND (power), 25 I/O0R (io), 26 I/O1R (io), 27 I/O2R (io), 28 I/O3R (io), 29 I/O4R (io), 30 I/O5R (io), 31 I/O6R (io), 32 I/O7R (io), 33 A9R (in), 34 A8R (in), 35 A7R (in), 36 A6R (in), 37 A5R (in), 38 A4R (in), 39 A3R (in), 40 A2R (in), 41 A1R (in), 42 A0R (in), 43 ~{OE}R (in), 44 A10R (in), 45 ~{BUSY}R (io), 46 R/~{W}R (in), 47 ~{CE}R (in), 48 VCC (power)

## CY7C142-45PI
designator U?
2K x 8 Dual-Port Static RAM
footprint P25 (DIP, Molded; 48 Leads; Row Spacing 15.24 mm; Pitch 2.54 mm)
3D model P25 (DIP, Molded; 48 Leads; Row Spacing 15.24 mm; Pitch 2.54 mm)
pins: 1 ~{CE}L (in), 2 R/~{W}L (in), 3 ~{BUSY}L (io), 4 A10L (in), 5 ~{OE}L (in), 6 A0L (in), 7 A1L (in), 8 A2L (in), 9 A3L (in), 10 A4L (in), 11 A5L (in), 12 A6L (in), 13 A7L (in), 14 A8L (in), 15 A9L (in), 16 I/O0L (io), 17 I/O1L (io), 18 I/O2L (io), 19 I/O3L (io), 20 I/O4L (io), 21 I/O5L (io), 22 I/O6L (io), 23 I/O7L (io), 24 GND (power), 25 I/O0R (io), 26 I/O1R (io), 27 I/O2R (io), 28 I/O3R (io), 29 I/O4R (io), 30 I/O5R (io), 31 I/O6R (io), 32 I/O7R (io), 33 A9R (in), 34 A8R (in), 35 A7R (in), 36 A6R (in), 37 A5R (in), 38 A4R (in), 39 A3R (in), 40 A2R (in), 41 A1R (in), 42 A0R (in), 43 ~{OE}R (in), 44 A10R (in), 45 ~{BUSY}R (io), 46 R/~{W}R (in), 47 ~{CE}R (in), 48 VCC (power)

## CY7C142-55DMB
designator U?
2K x 8 Dual-Port Static RAM
footprint D26 (DIP, Sidebraze; 48 Leads; Row Spacing 15.24 mm; Pitch 2.54 mm)
3D model P25 (DIP, Sidebraze; 48 Leads; Row Spacing 15.24 mm; Pitch 2.54 mm)
pins: 1 ~{CE}L (in), 2 R/~{W}L (in), 3 ~{BUSY}L (io), 4 A10L (in), 5 ~{OE}L (in), 6 A0L (in), 7 A1L (in), 8 A2L (in), 9 A3L (in), 10 A4L (in), 11 A5L (in), 12 A6L (in), 13 A7L (in), 14 A8L (in), 15 A9L (in), 16 I/O0L (io), 17 I/O1L (io), 18 I/O2L (io), 19 I/O3L (io), 20 I/O4L (io), 21 I/O5L (io), 22 I/O6L (io), 23 I/O7L (io), 24 GND (power), 25 I/O0R (io), 26 I/O1R (io), 27 I/O2R (io), 28 I/O3R (io), 29 I/O4R (io), 30 I/O5R (io), 31 I/O6R (io), 32 I/O7R (io), 33 A9R (in), 34 A8R (in), 35 A7R (in), 36 A6R (in), 37 A5R (in), 38 A4R (in), 39 A3R (in), 40 A2R (in), 41 A1R (in), 42 A0R (in), 43 ~{OE}R (in), 44 A10R (in), 45 ~{BUSY}R (io), 46 R/~{W}R (in), 47 ~{CE}R (in), 48 VCC (power)

## CY7C142-55PC
designator U?
2K x 8 Dual-Port Static RAM
footprint P25 (DIP, Molded; 48 Leads; Row Spacing 15.24 mm; Pitch 2.54 mm)
3D model P25 (DIP, Molded; 48 Leads; Row Spacing 15.24 mm; Pitch 2.54 mm)
pins: 1 ~{CE}L (in), 2 R/~{W}L (in), 3 ~{BUSY}L (io), 4 A10L (in), 5 ~{OE}L (in), 6 A0L (in), 7 A1L (in), 8 A2L (in), 9 A3L (in), 10 A4L (in), 11 A5L (in), 12 A6L (in), 13 A7L (in), 14 A8L (in), 15 A9L (in), 16 I/O0L (io), 17 I/O1L (io), 18 I/O2L (io), 19 I/O3L (io), 20 I/O4L (io), 21 I/O5L (io), 22 I/O6L (io), 23 I/O7L (io), 24 GND (power), 25 I/O0R (io), 26 I/O1R (io), 27 I/O2R (io), 28 I/O3R (io), 29 I/O4R (io), 30 I/O5R (io), 31 I/O6R (io), 32 I/O7R (io), 33 A9R (in), 34 A8R (in), 35 A7R (in), 36 A6R (in), 37 A5R (in), 38 A4R (in), 39 A3R (in), 40 A2R (in), 41 A1R (in), 42 A0R (in), 43 ~{OE}R (in), 44 A10R (in), 45 ~{BUSY}R (io), 46 R/~{W}R (in), 47 ~{CE}R (in), 48 VCC (power)

## CY7C142-55PI
designator U?
2K x 8 Dual-Port Static RAM
footprint P25 (DIP, Molded; 48 Leads; Row Spacing 15.24 mm; Pitch 2.54 mm)
3D model P25 (DIP, Molded; 48 Leads; Row Spacing 15.24 mm; Pitch 2.54 mm)
pins: 1 ~{CE}L (in), 2 R/~{W}L (in), 3 ~{BUSY}L (io), 4 A10L (in), 5 ~{OE}L (in), 6 A0L (in), 7 A1L (in), 8 A2L (in), 9 A3L (in), 10 A4L (in), 11 A5L (in), 12 A6L (in), 13 A7L (in), 14 A8L (in), 15 A9L (in), 16 I/O0L (io), 17 I/O1L (io), 18 I/O2L (io), 19 I/O3L (io), 20 I/O4L (io), 21 I/O5L (io), 22 I/O6L (io), 23 I/O7L (io), 24 GND (power), 25 I/O0R (io), 26 I/O1R (io), 27 I/O2R (io), 28 I/O3R (io), 29 I/O4R (io), 30 I/O5R (io), 31 I/O6R (io), 32 I/O7R (io), 33 A9R (in), 34 A8R (in), 35 A7R (in), 36 A6R (in), 37 A5R (in), 38 A4R (in), 39 A3R (in), 40 A2R (in), 41 A1R (in), 42 A0R (in), 43 ~{OE}R (in), 44 A10R (in), 45 ~{BUSY}R (io), 46 R/~{W}R (in), 47 ~{CE}R (in), 48 VCC (power)

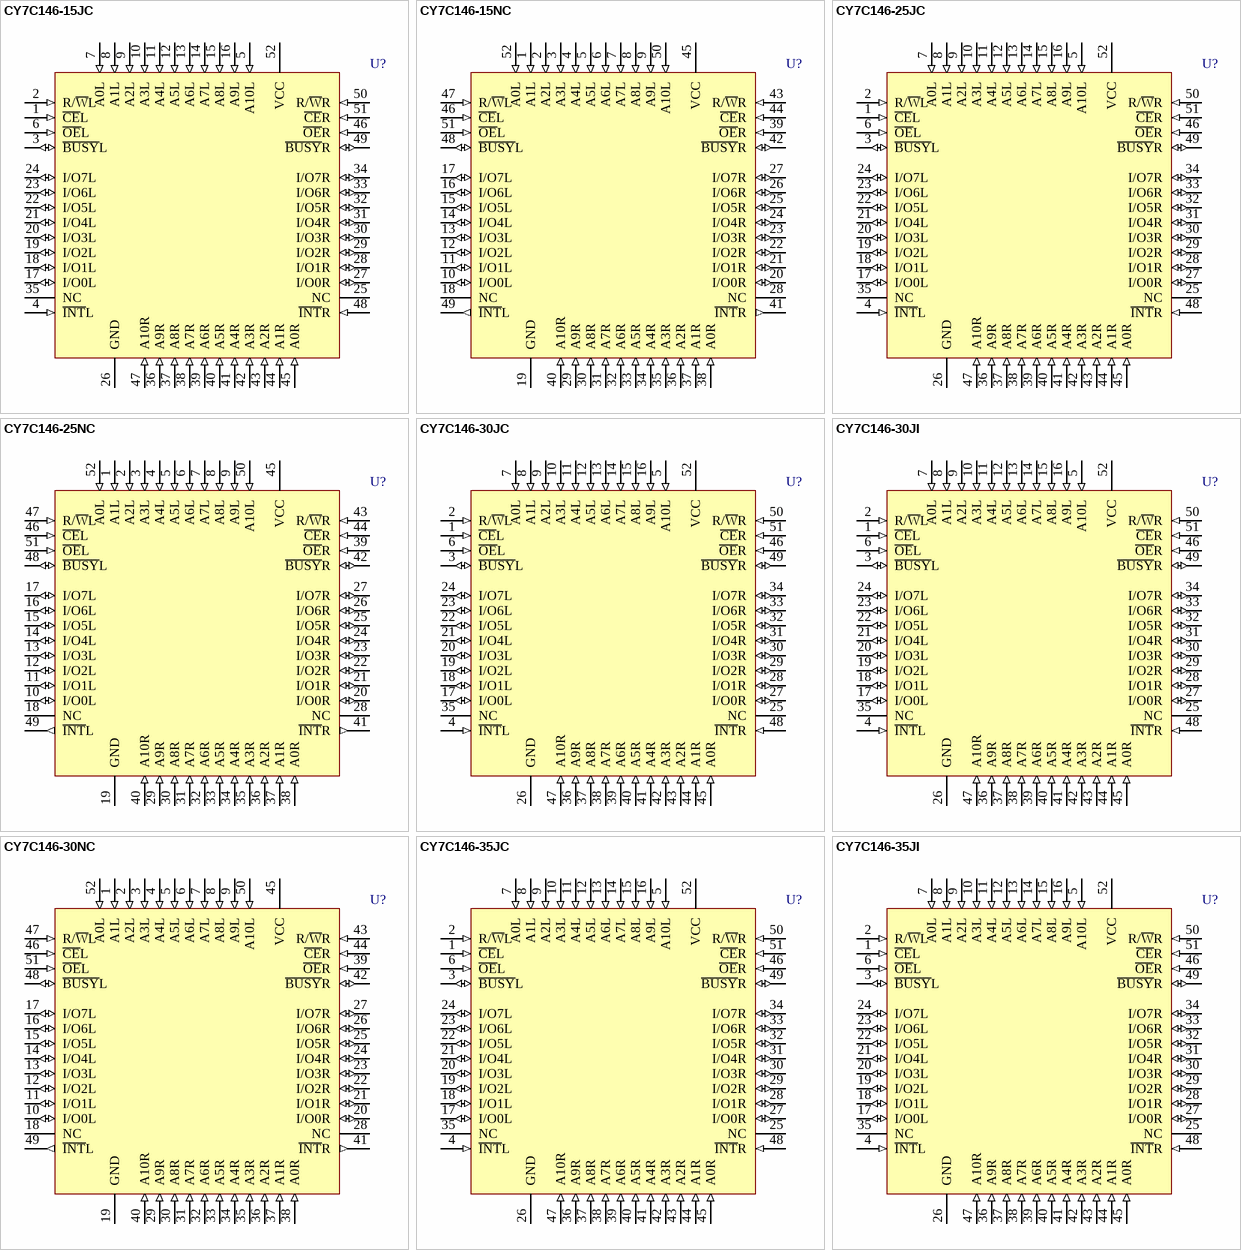
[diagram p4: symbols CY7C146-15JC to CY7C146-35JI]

## CY7C146-15JC
designator U?
2K x 8 Dual-Port Static RAM
footprint J69_N (Leaded Chip Carrier, 52-Leads, Body 19x19mm, Pitch 1.27mm, IPC Medium Density)
footprint J69_L (Leaded Chip Carrier, 52-Leads, Body 19x19mm, Pitch 1.27mm, IPC High Density)
footprint J69_M (Leaded Chip Carrier, 52-Leads, Body 19x19mm, Pitch 1.27mm, IPC Low Density)
3D model CY7C146-J69 (52-Pin Plastic Leaded Chip Carrier 1.27 mm Pitch)
pins: 1 ~{CE}L (in), 2 R/~{W}L (in), 3 ~{BUSY}L (io), 4 ~{INT}L (in), 5 A10L (in), 6 ~{OE}L (in), 7 A0L (in), 8 A1L (in), 9 A2L (in), 10 A3L (in), 11 A4L (in), 12 A5L (in), 13 A6L (in), 14 A7L (in), 15 A8L (in), 16 A9L (in), 17 I/O0L (io), 18 I/O1L (io), 19 I/O2L (io), 20 I/O3L (io), 21 I/O4L (io), 22 I/O5L (io), 23 I/O6L (io), 24 I/O7L (io), 25 NC, 26 GND (power), 27 I/O0R (io), 28 I/O1R (io), 29 I/O2R (io), 30 I/O3R (io), 31 I/O4R (io), 32 I/O5R (io), 33 I/O6R (io), 34 I/O7R (io), 35 NC, 36 A9R (in), 37 A8R (in), 38 A7R (in), 39 A6R (in), 40 A5R (in), 41 A4R (in), 42 A3R (in), 43 A2R (in), 44 A1R (in), 45 A0R (in), 46 ~{OE}R (in), 47 A10R (in), 48 ~{INT}R (in), 49 ~{BUSY}R (io), 50 R/~{W}R (in), 51 ~{CE}R (in), 52 VCC (power)

## CY7C146-15NC
designator U?
2K x 8 Dual-Port Static RAM
footprint N52_N (QFP, 52-Leads, Body 10 x 10mm, Pitch 0.65mm, IPC Medium Density)
footprint N52_L (QFP, 52-Leads, Body 10 x 10mm, Pitch 0.65mm, IPC High Density)
footprint N52_M (QFP, 52-Leads, Body 10 x 10mm, Pitch 0.65mm, IPC Low Density)
3D model CY7C146-N52 (52-Pin Plastic Quad Flat Pack 0.65 mm Pitch)
pins: 1 A1L (in), 2 A2L (in), 3 A3L (in), 4 A4L (in), 5 A5L (in), 6 A6L (in), 7 A7L (in), 8 A8L (in), 9 A9L (in), 10 I/O0L (io), 11 I/O1L (io), 12 I/O2L (io), 13 I/O3L (io), 14 I/O4L (io), 15 I/O5L (io), 16 I/O6L (io), 17 I/O7L (io), 18 NC, 19 GND (power), 20 I/O0R (io), 21 I/O1R (io), 22 I/O2R (io), 23 I/O3R (io), 24 I/O4R (io), 25 I/O5R (io), 26 I/O6R (io), 27 I/O7R (io), 28 NC, 29 A9R (in), 30 A8R (in), 31 A7R (in), 32 A6R (in), 33 A5R (in), 34 A4R (in), 35 A3R (in), 36 A2R (in), 37 A1R (in), 38 A0R (in), 39 ~{OE}R (in), 40 A10R (in), 41 ~{INT}R (out), 42 ~{BUSY}R (io), 43 R/~{W}R (in), 44 ~{CE}R (in), 45 VCC (power), 46 ~{CE}L (in), 47 R/~{W}L (in), 48 ~{BUSY}L (io), 49 ~{INT}L (out), 50 A10L (in), 51 ~{OE}L (in), 52 A0L (in)

## CY7C146-25JC
designator U?
2K x 8 Dual-Port Static RAM
footprint J69_N (Leaded Chip Carrier, 52-Leads, Body 19x19mm, Pitch 1.27mm, IPC Medium Density)
footprint J69_L (Leaded Chip Carrier, 52-Leads, Body 19x19mm, Pitch 1.27mm, IPC High Density)
footprint J69_M (Leaded Chip Carrier, 52-Leads, Body 19x19mm, Pitch 1.27mm, IPC Low Density)
3D model CY7C146-J69 (52-Pin Plastic Leaded Chip Carrier 1.27 mm Pitch)
pins: 1 ~{CE}L (in), 2 R/~{W}L (in), 3 ~{BUSY}L (io), 4 ~{INT}L (in), 5 A10L (in), 6 ~{OE}L (in), 7 A0L (in), 8 A1L (in), 9 A2L (in), 10 A3L (in), 11 A4L (in), 12 A5L (in), 13 A6L (in), 14 A7L (in), 15 A8L (in), 16 A9L (in), 17 I/O0L (io), 18 I/O1L (io), 19 I/O2L (io), 20 I/O3L (io), 21 I/O4L (io), 22 I/O5L (io), 23 I/O6L (io), 24 I/O7L (io), 25 NC, 26 GND (power), 27 I/O0R (io), 28 I/O1R (io), 29 I/O2R (io), 30 I/O3R (io), 31 I/O4R (io), 32 I/O5R (io), 33 I/O6R (io), 34 I/O7R (io), 35 NC, 36 A9R (in), 37 A8R (in), 38 A7R (in), 39 A6R (in), 40 A5R (in), 41 A4R (in), 42 A3R (in), 43 A2R (in), 44 A1R (in), 45 A0R (in), 46 ~{OE}R (in), 47 A10R (in), 48 ~{INT}R (in), 49 ~{BUSY}R (io), 50 R/~{W}R (in), 51 ~{CE}R (in), 52 VCC (power)

## CY7C146-25NC
designator U?
2K x 8 Dual-Port Static RAM
footprint N52_N (QFP, 52-Leads, Body 10 x 10mm, Pitch 0.65mm, IPC Medium Density)
footprint N52_L (QFP, 52-Leads, Body 10 x 10mm, Pitch 0.65mm, IPC High Density)
footprint N52_M (QFP, 52-Leads, Body 10 x 10mm, Pitch 0.65mm, IPC Low Density)
3D model CY7C146-N52 (52-Pin Plastic Quad Flat Pack 0.65 mm Pitch)
pins: 1 A1L (in), 2 A2L (in), 3 A3L (in), 4 A4L (in), 5 A5L (in), 6 A6L (in), 7 A7L (in), 8 A8L (in), 9 A9L (in), 10 I/O0L (io), 11 I/O1L (io), 12 I/O2L (io), 13 I/O3L (io), 14 I/O4L (io), 15 I/O5L (io), 16 I/O6L (io), 17 I/O7L (io), 18 NC, 19 GND (power), 20 I/O0R (io), 21 I/O1R (io), 22 I/O2R (io), 23 I/O3R (io), 24 I/O4R (io), 25 I/O5R (io), 26 I/O6R (io), 27 I/O7R (io), 28 NC, 29 A9R (in), 30 A8R (in), 31 A7R (in), 32 A6R (in), 33 A5R (in), 34 A4R (in), 35 A3R (in), 36 A2R (in), 37 A1R (in), 38 A0R (in), 39 ~{OE}R (in), 40 A10R (in), 41 ~{INT}R (out), 42 ~{BUSY}R (io), 43 R/~{W}R (in), 44 ~{CE}R (in), 45 VCC (power), 46 ~{CE}L (in), 47 R/~{W}L (in), 48 ~{BUSY}L (io), 49 ~{INT}L (out), 50 A10L (in), 51 ~{OE}L (in), 52 A0L (in)

## CY7C146-30JC
designator U?
2K x 8 Dual-Port Static RAM
footprint J69_N (Leaded Chip Carrier, 52-Leads, Body 19x19mm, Pitch 1.27mm, IPC Medium Density)
footprint J69_L (Leaded Chip Carrier, 52-Leads, Body 19x19mm, Pitch 1.27mm, IPC High Density)
footprint J69_M (Leaded Chip Carrier, 52-Leads, Body 19x19mm, Pitch 1.27mm, IPC Low Density)
3D model CY7C146-J69 (52-Pin Plastic Leaded Chip Carrier 1.27 mm Pitch)
pins: 1 ~{CE}L (in), 2 R/~{W}L (in), 3 ~{BUSY}L (io), 4 ~{INT}L (in), 5 A10L (in), 6 ~{OE}L (in), 7 A0L (in), 8 A1L (in), 9 A2L (in), 10 A3L (in), 11 A4L (in), 12 A5L (in), 13 A6L (in), 14 A7L (in), 15 A8L (in), 16 A9L (in), 17 I/O0L (io), 18 I/O1L (io), 19 I/O2L (io), 20 I/O3L (io), 21 I/O4L (io), 22 I/O5L (io), 23 I/O6L (io), 24 I/O7L (io), 25 NC, 26 GND (power), 27 I/O0R (io), 28 I/O1R (io), 29 I/O2R (io), 30 I/O3R (io), 31 I/O4R (io), 32 I/O5R (io), 33 I/O6R (io), 34 I/O7R (io), 35 NC, 36 A9R (in), 37 A8R (in), 38 A7R (in), 39 A6R (in), 40 A5R (in), 41 A4R (in), 42 A3R (in), 43 A2R (in), 44 A1R (in), 45 A0R (in), 46 ~{OE}R (in), 47 A10R (in), 48 ~{INT}R (in), 49 ~{BUSY}R (io), 50 R/~{W}R (in), 51 ~{CE}R (in), 52 VCC (power)

## CY7C146-30JI
designator U?
2K x 8 Dual-Port Static RAM
footprint J69_N (Leaded Chip Carrier, 52-Leads, Body 19x19mm, Pitch 1.27mm, IPC Medium Density)
footprint J69_L (Leaded Chip Carrier, 52-Leads, Body 19x19mm, Pitch 1.27mm, IPC High Density)
footprint J69_M (Leaded Chip Carrier, 52-Leads, Body 19x19mm, Pitch 1.27mm, IPC Low Density)
3D model CY7C146-J69 (52-Pin Plastic Leaded Chip Carrier 1.27 mm Pitch)
pins: 1 ~{CE}L (in), 2 R/~{W}L (in), 3 ~{BUSY}L (io), 4 ~{INT}L (in), 5 A10L (in), 6 ~{OE}L (in), 7 A0L (in), 8 A1L (in), 9 A2L (in), 10 A3L (in), 11 A4L (in), 12 A5L (in), 13 A6L (in), 14 A7L (in), 15 A8L (in), 16 A9L (in), 17 I/O0L (io), 18 I/O1L (io), 19 I/O2L (io), 20 I/O3L (io), 21 I/O4L (io), 22 I/O5L (io), 23 I/O6L (io), 24 I/O7L (io), 25 NC, 26 GND (power), 27 I/O0R (io), 28 I/O1R (io), 29 I/O2R (io), 30 I/O3R (io), 31 I/O4R (io), 32 I/O5R (io), 33 I/O6R (io), 34 I/O7R (io), 35 NC, 36 A9R (in), 37 A8R (in), 38 A7R (in), 39 A6R (in), 40 A5R (in), 41 A4R (in), 42 A3R (in), 43 A2R (in), 44 A1R (in), 45 A0R (in), 46 ~{OE}R (in), 47 A10R (in), 48 ~{INT}R (in), 49 ~{BUSY}R (io), 50 R/~{W}R (in), 51 ~{CE}R (in), 52 VCC (power)

## CY7C146-30NC
designator U?
2K x 8 Dual-Port Static RAM
footprint N52_N (QFP, 52-Leads, Body 10 x 10mm, Pitch 0.65mm, IPC Medium Density)
footprint N52_L (QFP, 52-Leads, Body 10 x 10mm, Pitch 0.65mm, IPC High Density)
footprint N52_M (QFP, 52-Leads, Body 10 x 10mm, Pitch 0.65mm, IPC Low Density)
3D model CY7C146-N52 (52-Pin Plastic Quad Flat Pack 0.65 mm Pitch)
pins: 1 A1L (in), 2 A2L (in), 3 A3L (in), 4 A4L (in), 5 A5L (in), 6 A6L (in), 7 A7L (in), 8 A8L (in), 9 A9L (in), 10 I/O0L (io), 11 I/O1L (io), 12 I/O2L (io), 13 I/O3L (io), 14 I/O4L (io), 15 I/O5L (io), 16 I/O6L (io), 17 I/O7L (io), 18 NC, 19 GND (power), 20 I/O0R (io), 21 I/O1R (io), 22 I/O2R (io), 23 I/O3R (io), 24 I/O4R (io), 25 I/O5R (io), 26 I/O6R (io), 27 I/O7R (io), 28 NC, 29 A9R (in), 30 A8R (in), 31 A7R (in), 32 A6R (in), 33 A5R (in), 34 A4R (in), 35 A3R (in), 36 A2R (in), 37 A1R (in), 38 A0R (in), 39 ~{OE}R (in), 40 A10R (in), 41 ~{INT}R (out), 42 ~{BUSY}R (io), 43 R/~{W}R (in), 44 ~{CE}R (in), 45 VCC (power), 46 ~{CE}L (in), 47 R/~{W}L (in), 48 ~{BUSY}L (io), 49 ~{INT}L (out), 50 A10L (in), 51 ~{OE}L (in), 52 A0L (in)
